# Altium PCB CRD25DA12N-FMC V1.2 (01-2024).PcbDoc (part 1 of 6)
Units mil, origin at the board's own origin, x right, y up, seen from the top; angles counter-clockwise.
Board outline 8000 x 8000 mil, 6 copper layers (Top Layer, Layer 2, Layer 3, Layer 4, Layer 5, Bottom Layer), stack 91 mil thick; 574 components, 325 nets, 1631 pads, 633 vias.
Unrouted connection lines stored in the file: 1.
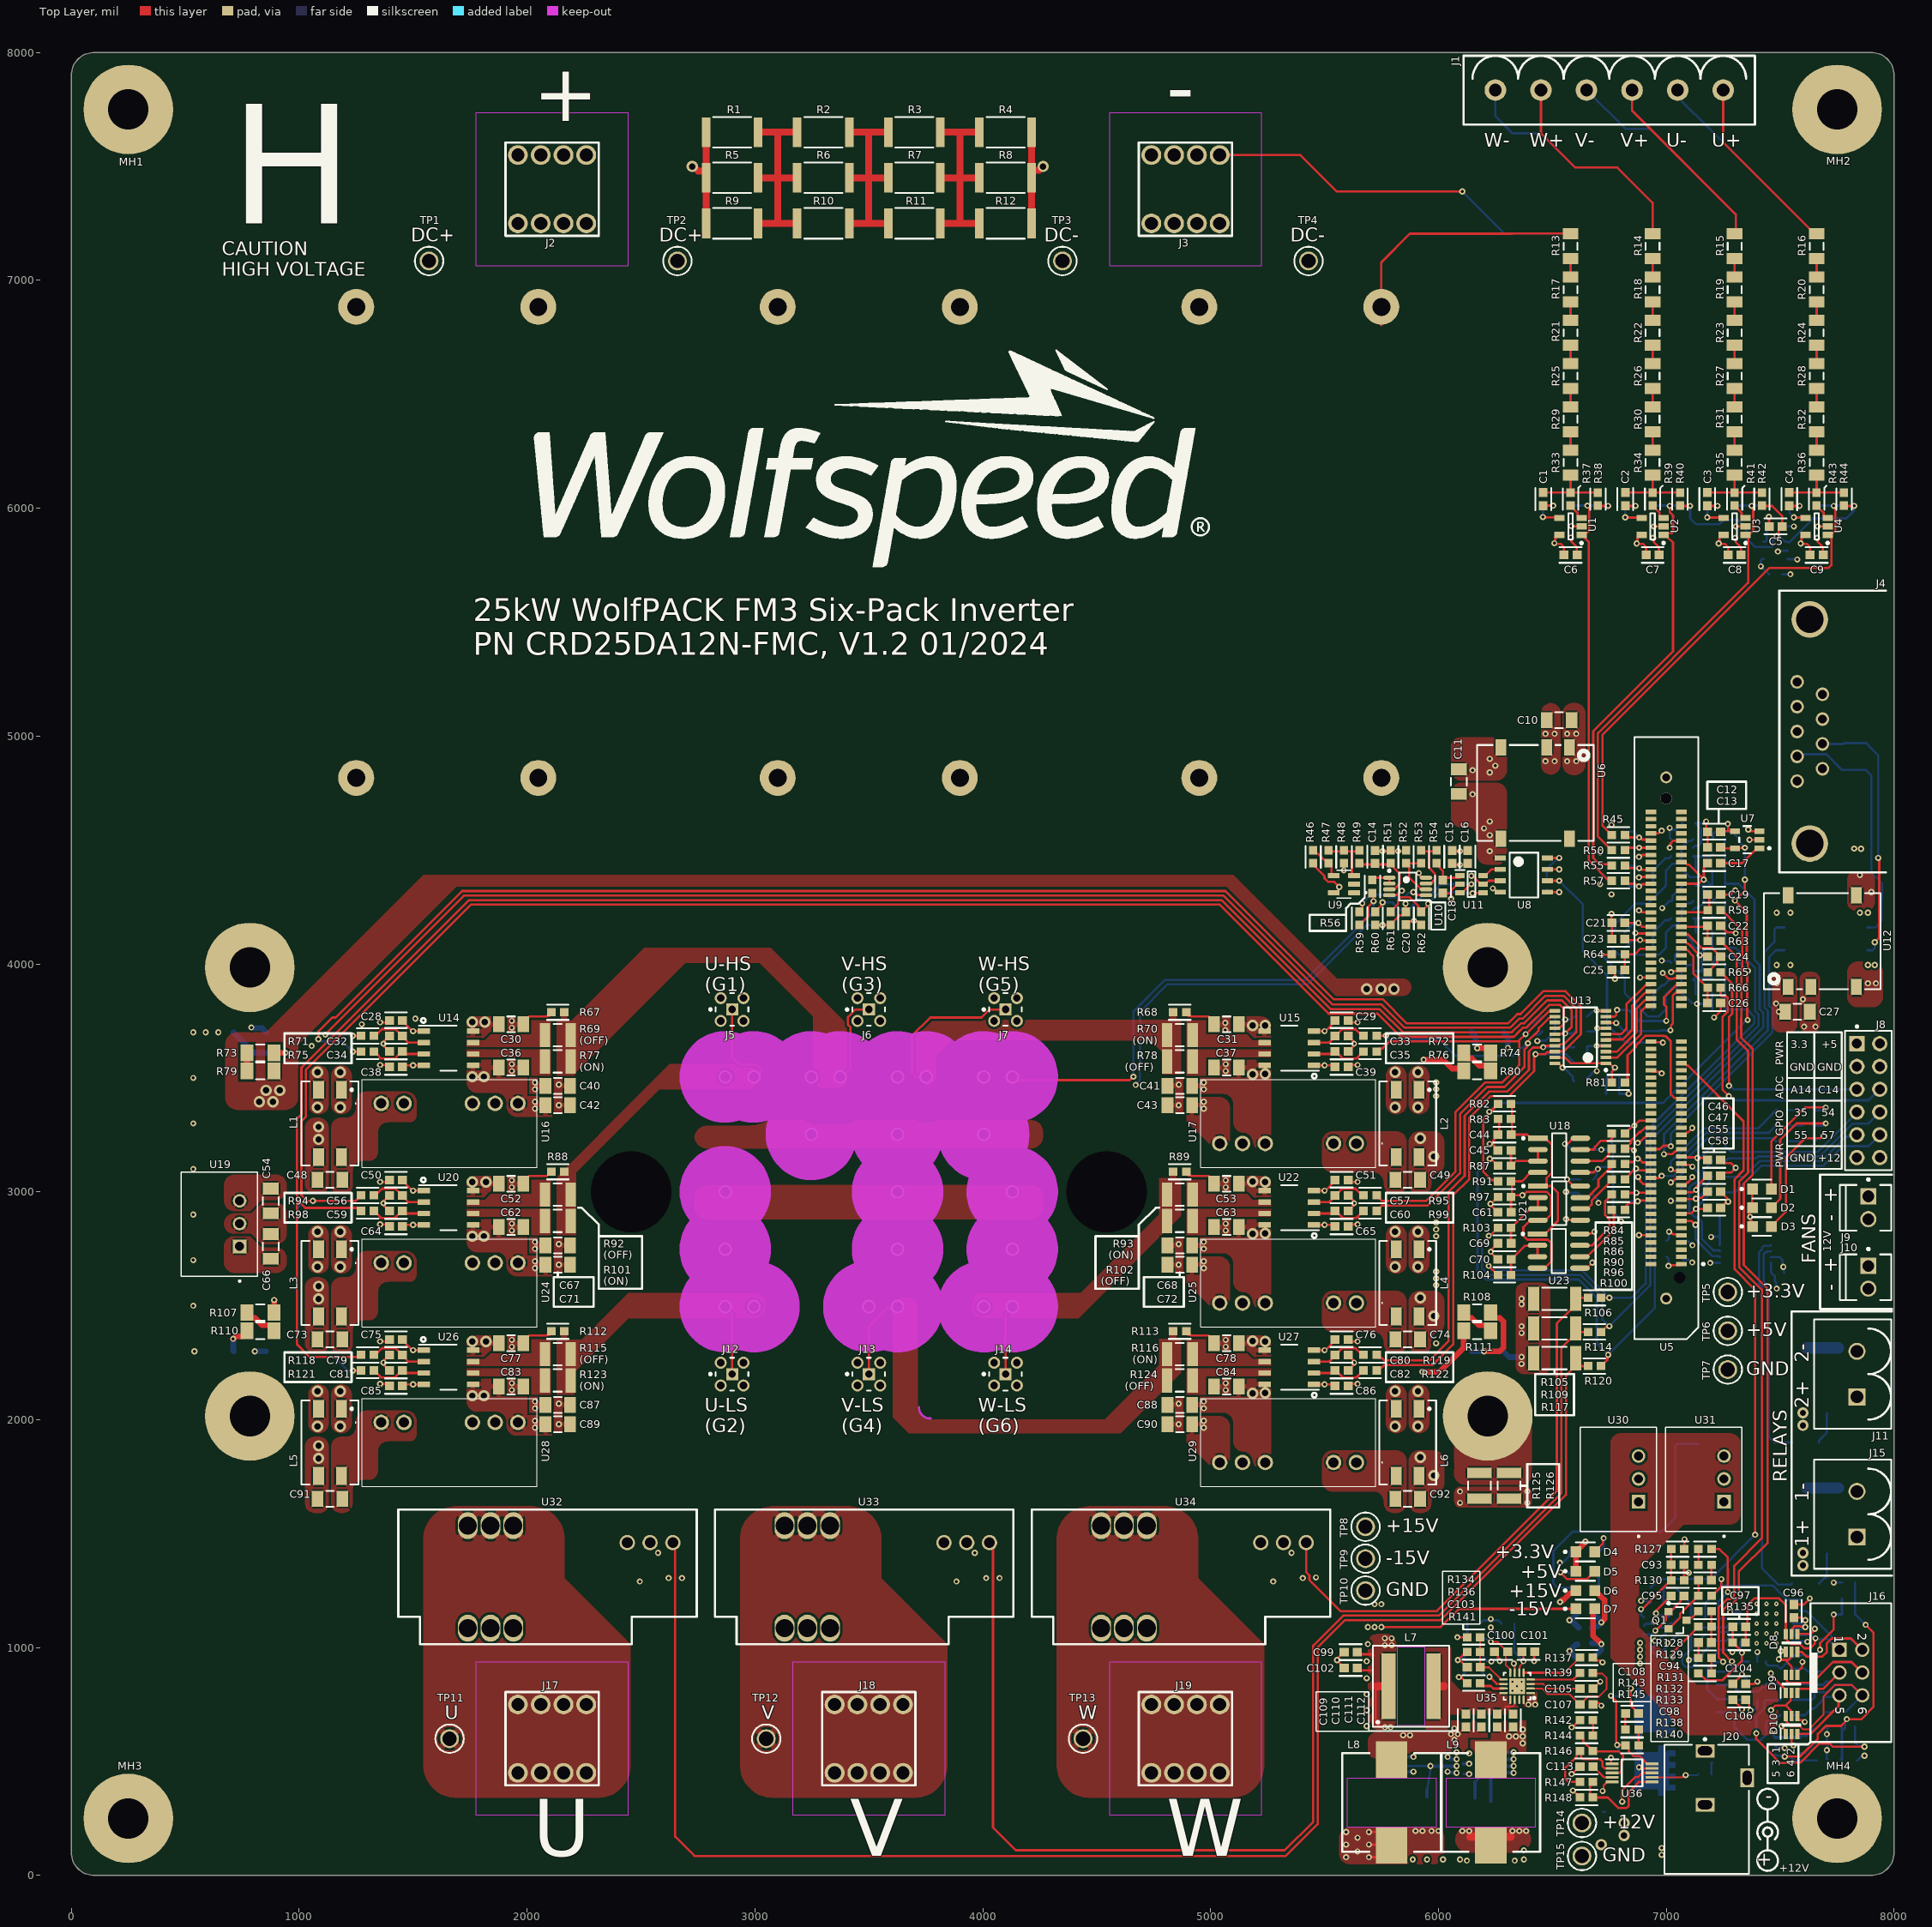
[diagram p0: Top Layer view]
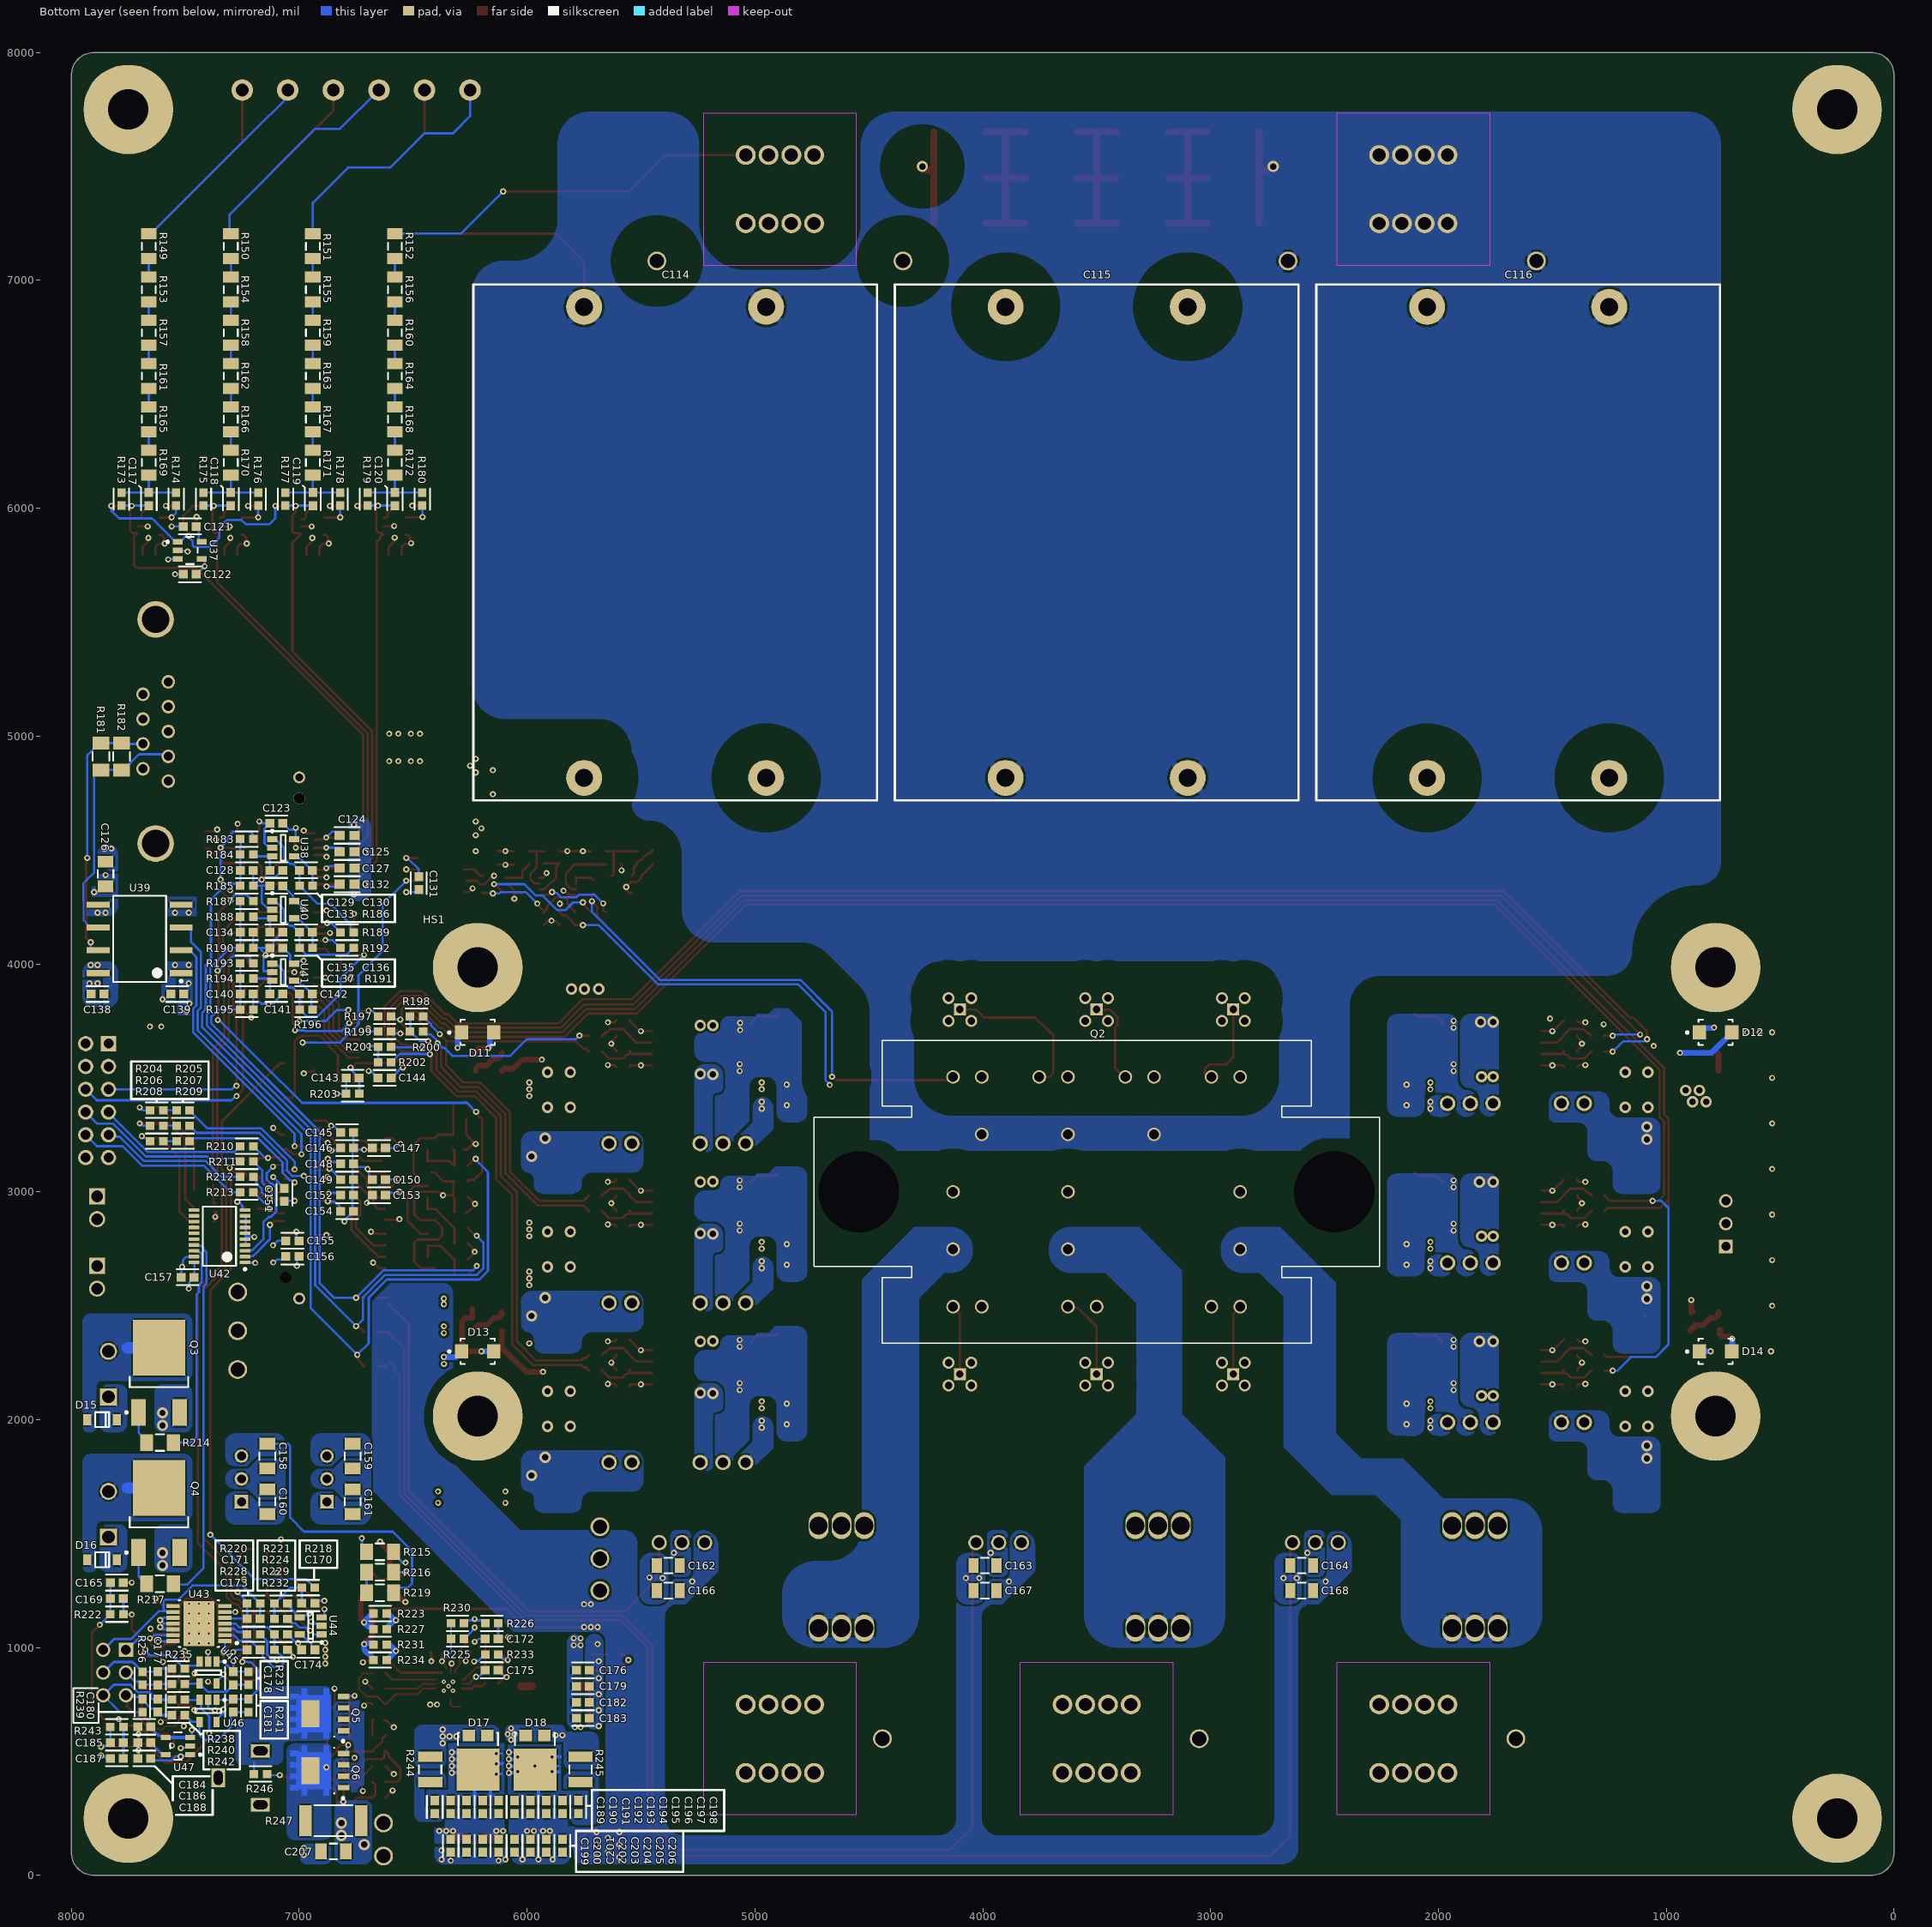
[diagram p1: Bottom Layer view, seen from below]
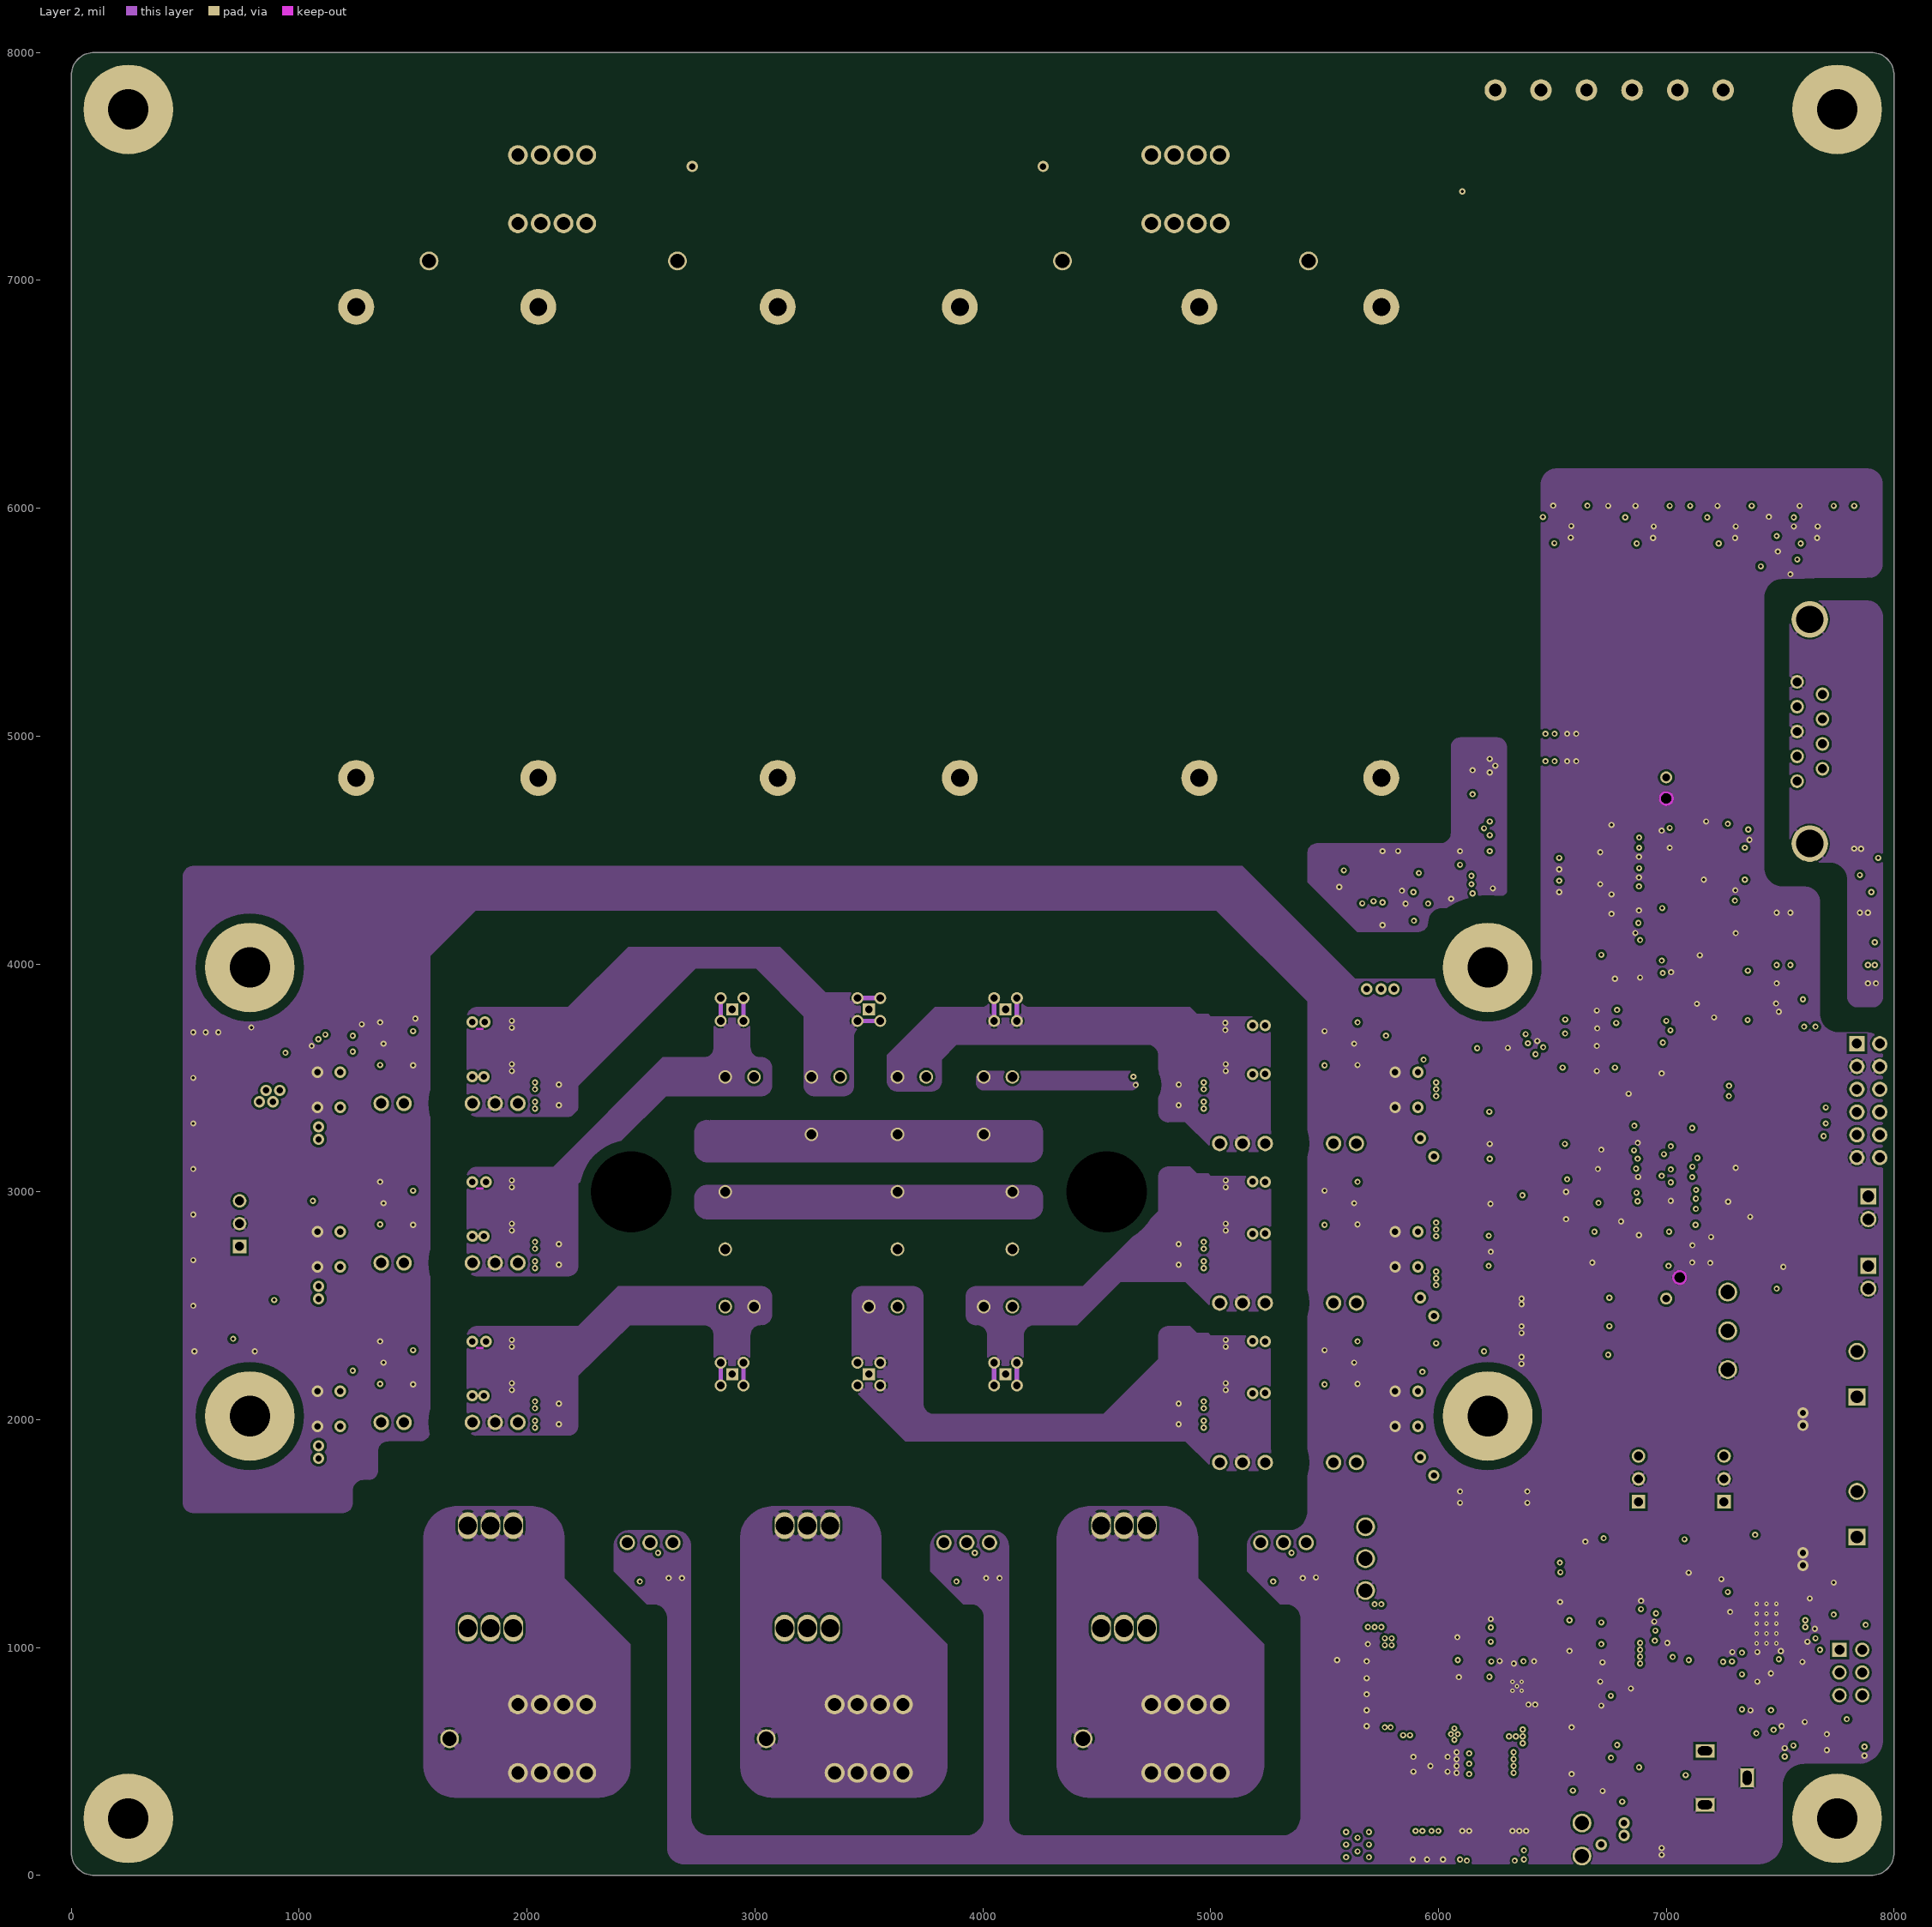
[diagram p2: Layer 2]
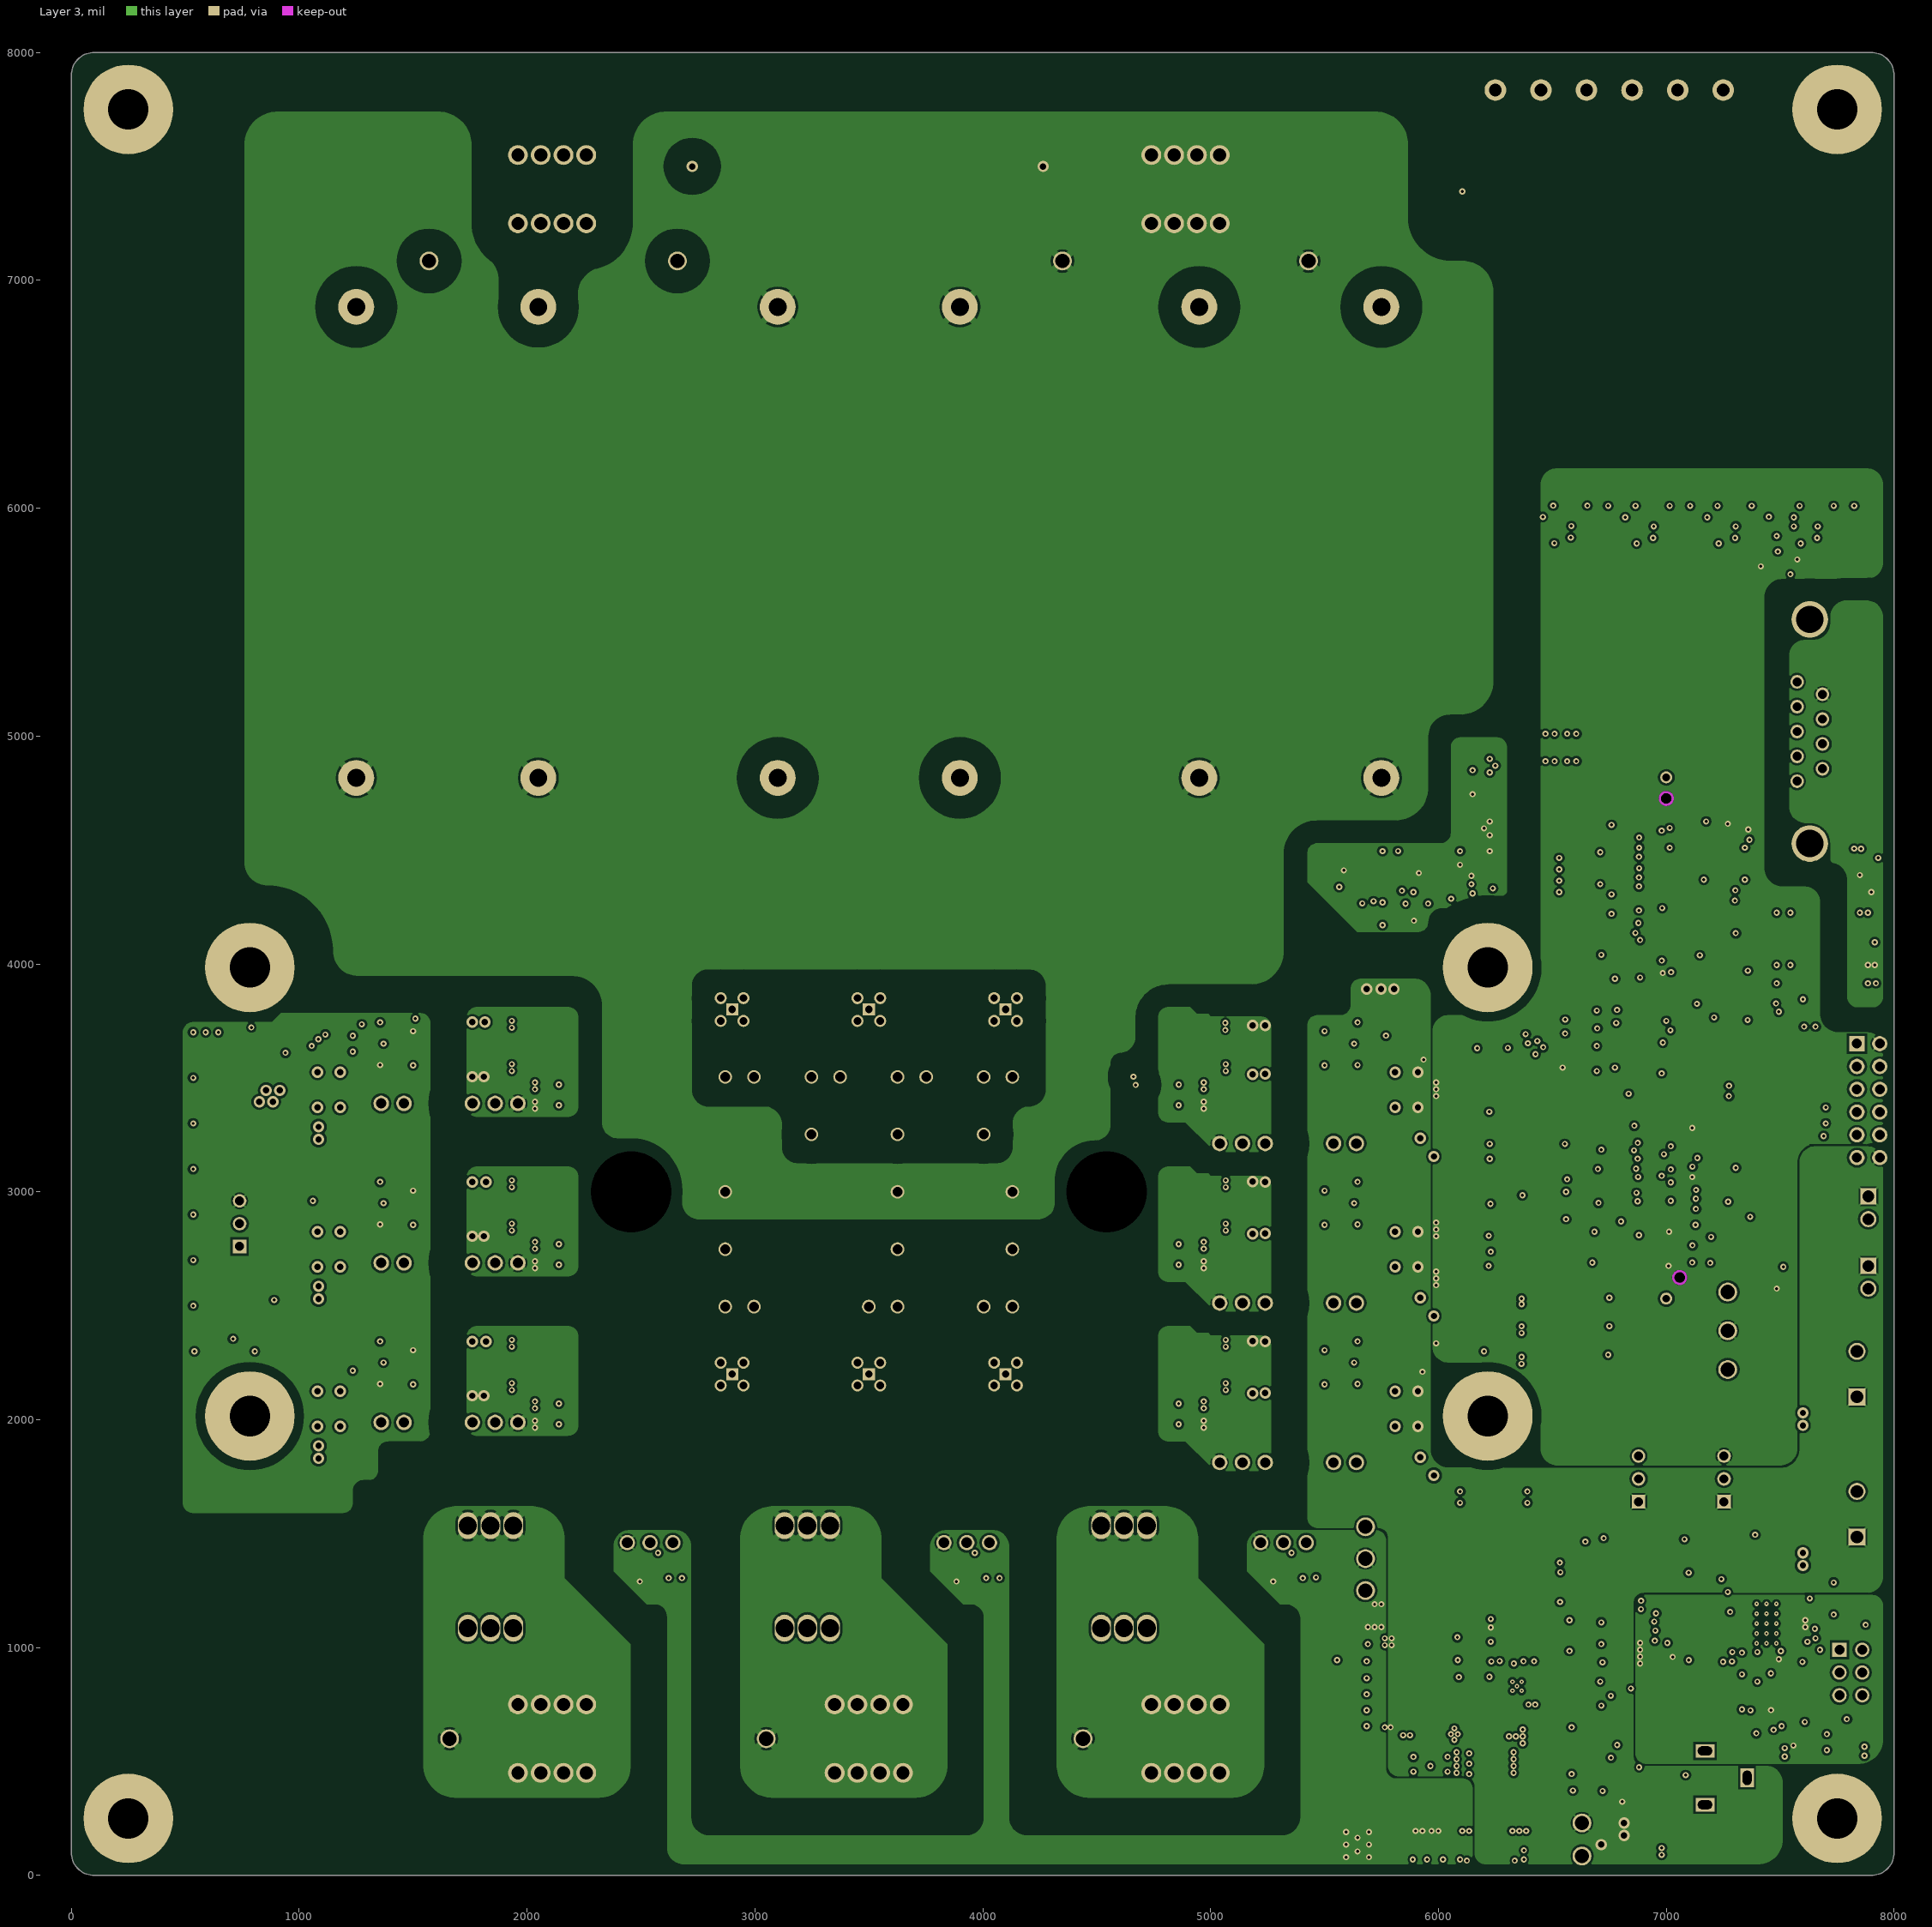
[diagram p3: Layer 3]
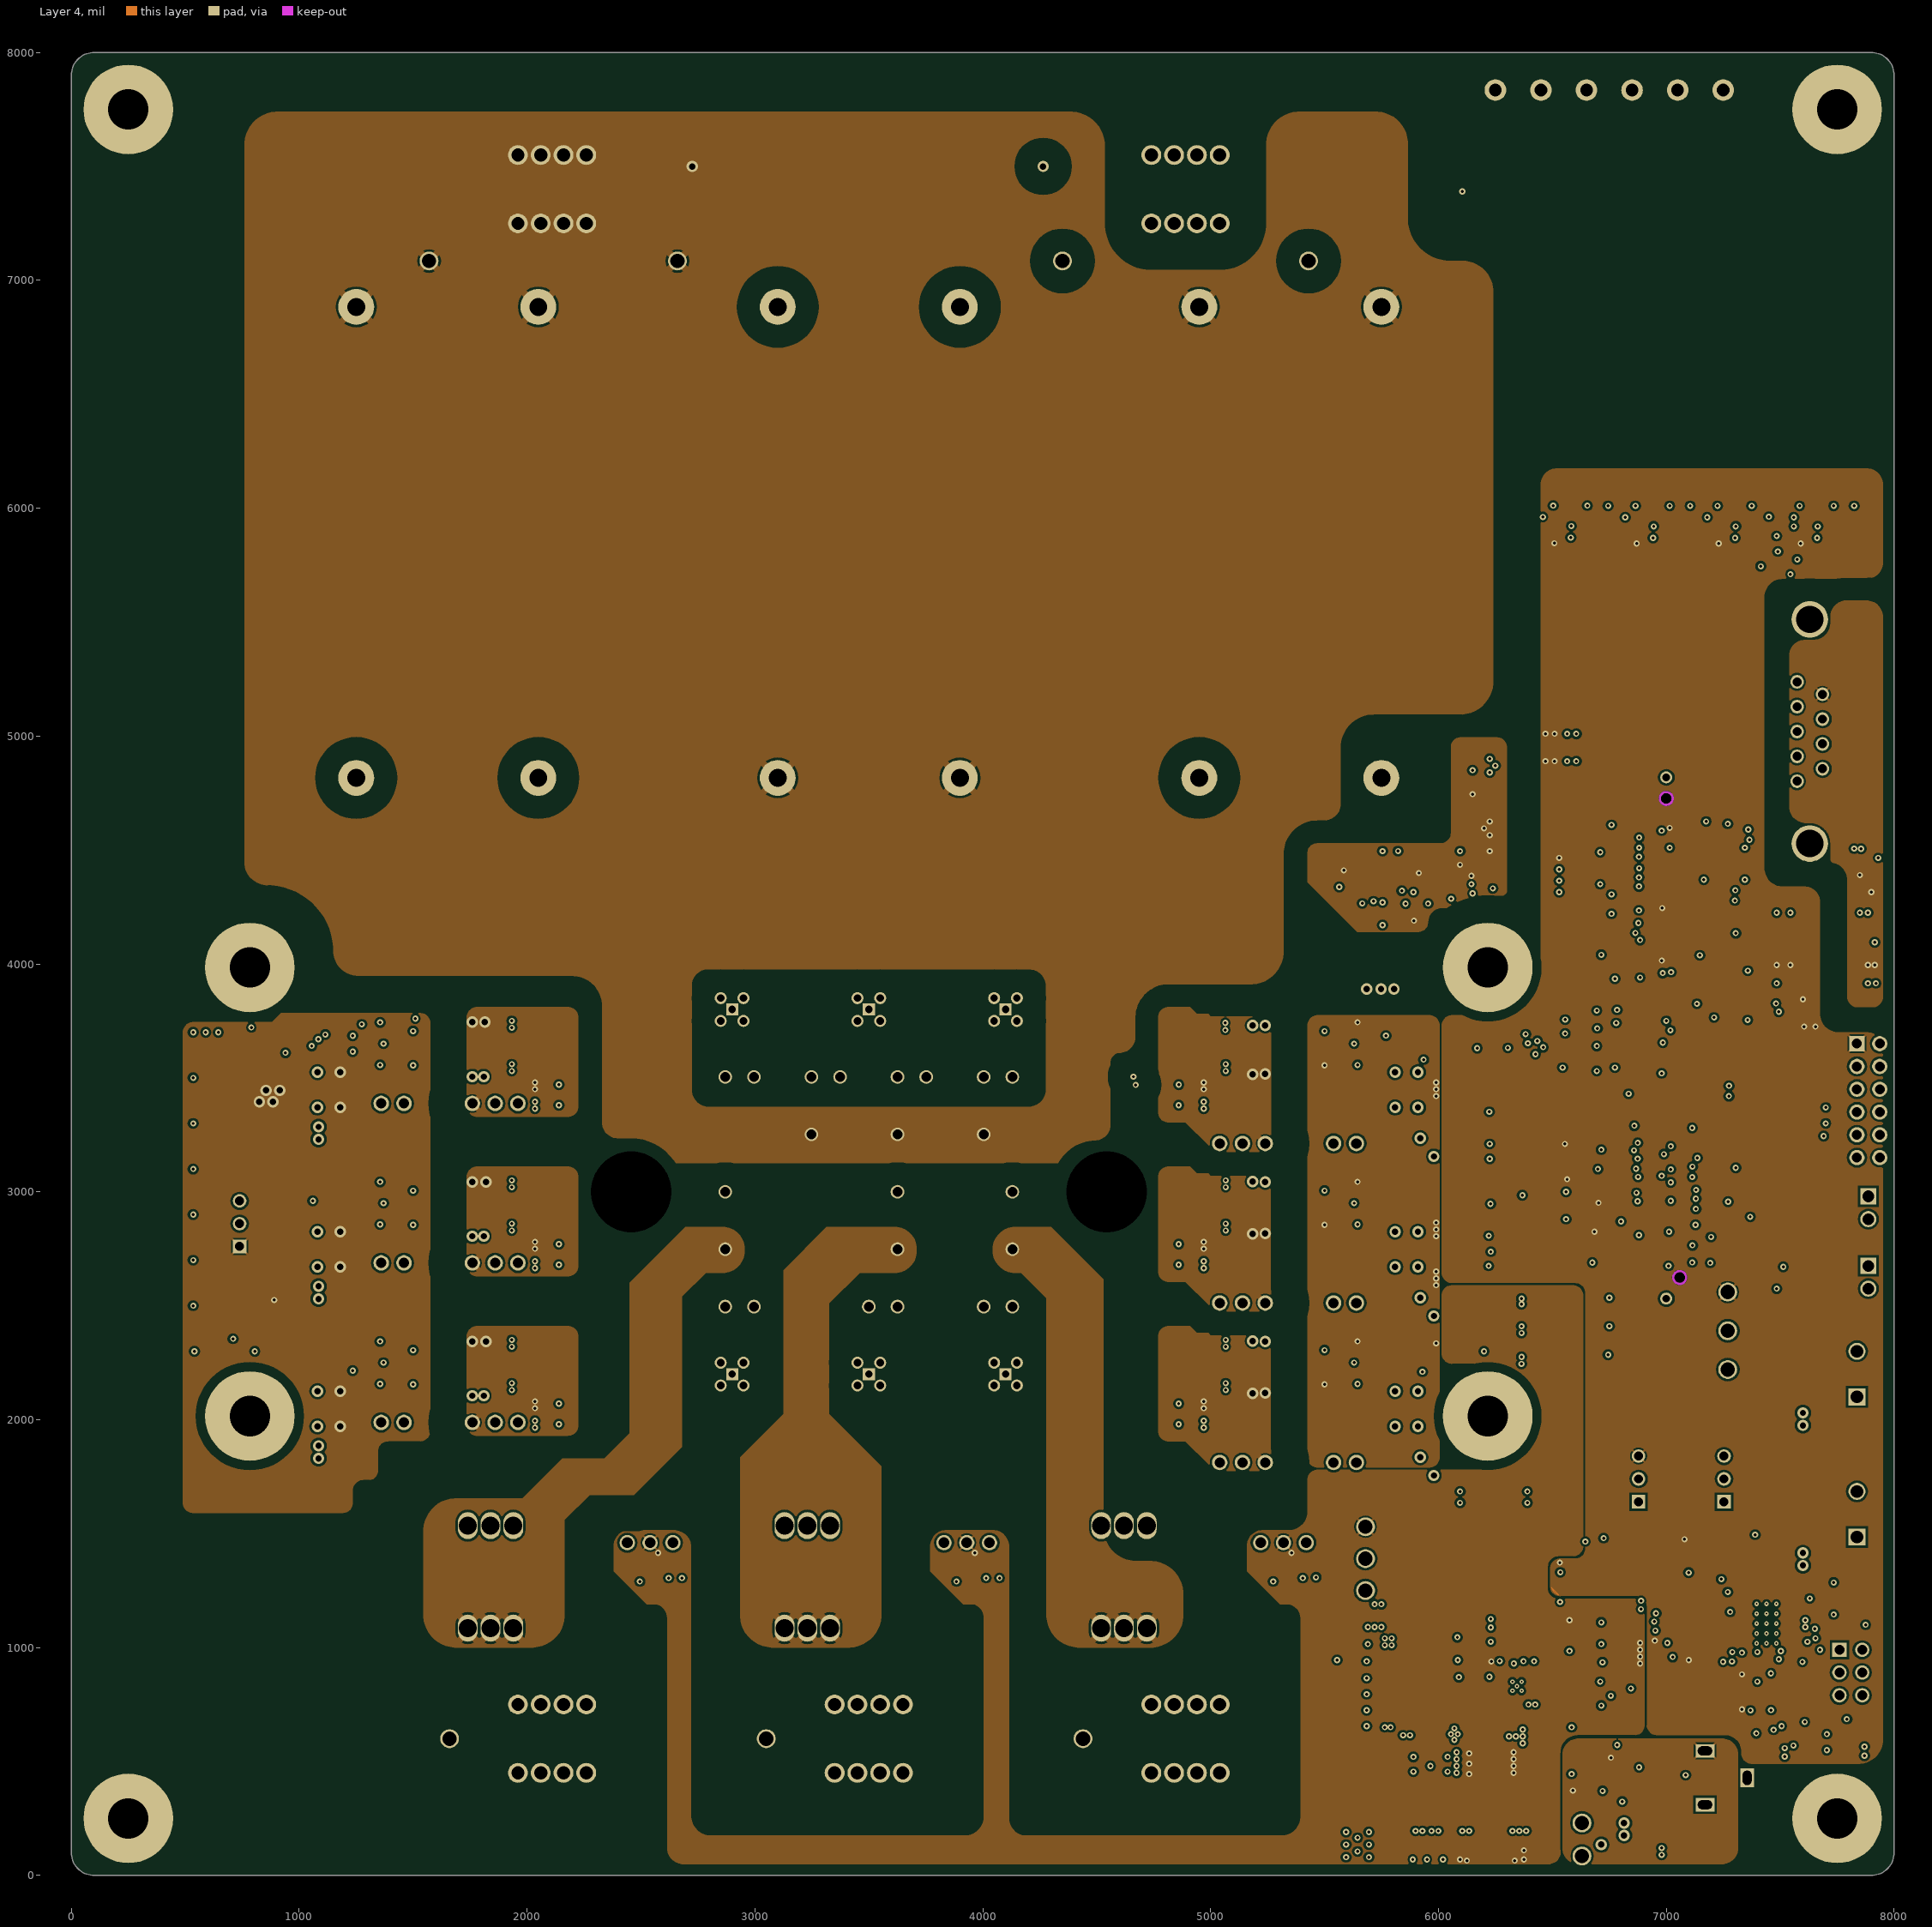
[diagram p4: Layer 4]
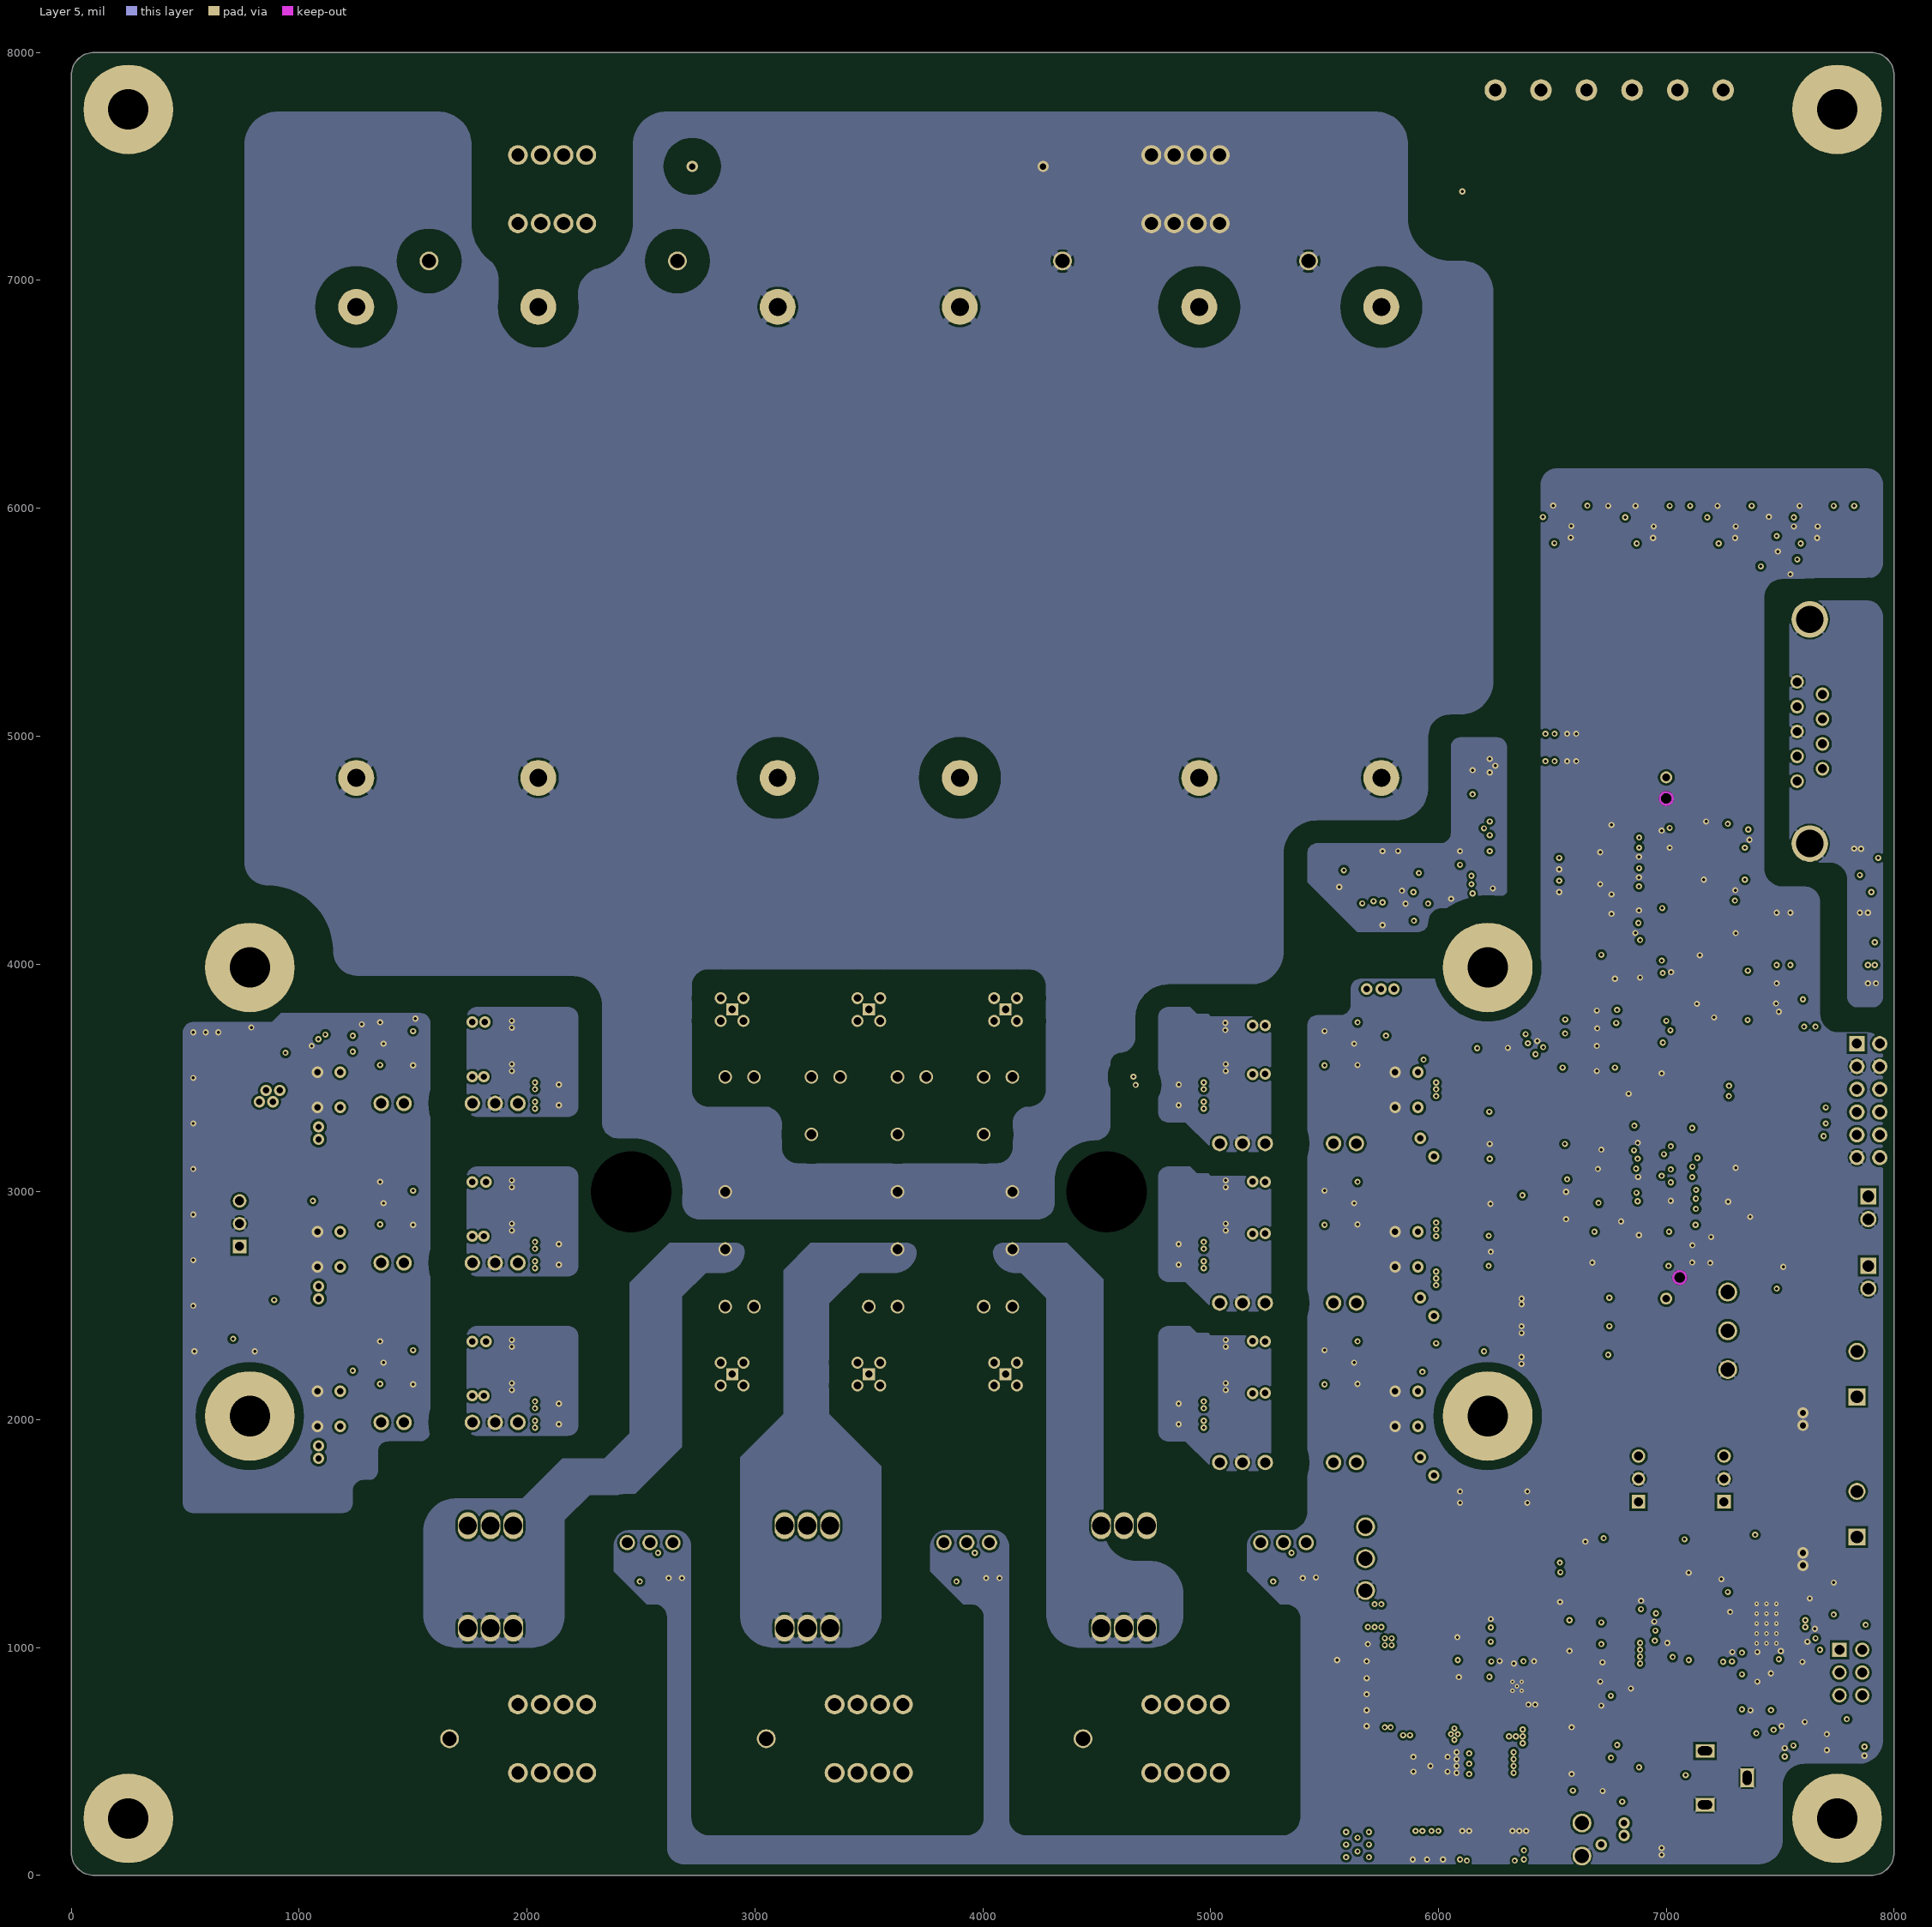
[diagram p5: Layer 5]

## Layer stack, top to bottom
Top Solder: solder mask 1, SM-002, Dk 4
Top Layer: signal copper 2.756
Dielectric 2: prepreg 7.894, PP-006, Dk 4.1
Layer 2: signal copper 2.756
Dielectric 4: prepreg 7.894, PP-006, Dk 4.1
Layer 3: signal copper 2.756
Dielectric 1: dielectric 42.888, FR-4, Dk 4.8
Layer 4: signal copper 2.756
Dielectric 5: prepreg 7.894, PP-006, Dk 4.1
Layer 5: signal copper 2.756
Dielectric 3: prepreg 7.894, PP-006, Dk 4.1
Bottom Layer: signal copper 2.756
Bottom Solder: solder mask 1, SM-002, Dk 4

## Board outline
0,100 0,7900 cw(c100,7900) 100,8000 7900,8000 cw(c7900,7900) 8000,7900 8000,100 cw(c7900,100) 7900,0 100,0 cw(c100,100)

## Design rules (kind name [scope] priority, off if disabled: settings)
Clearance Keepout [IsKeepOut] p1: gap=0 ignorepadtopadclearanceinfootprint=FALSE
Clearance DC+/-_Heatsink [InNet('DC-') Or InNet('DC+') vs HasFootprint('LA 6 150 12')] p2: gap=160 ignorepadtopadclearanceinfootprint=FALSE except(0: Arc-Hole Track-Hole SMDPad-Hole THPad-Hole Via-Hole Fill-Hole Poly-Hole Region-Hole Text-Hole)
Clearance NTC_Heatsink [InNetClass('NTC Class') vs HasFootprint('LA 6 150 12')] p3: gap=120 ignorepadtopadclearanceinfootprint=FALSE except(0: Arc-Hole Track-Hole SMDPad-Hole THPad-Hole Via-Hole Fill-Hole Poly-Hole Region-Hole Text-Hole)
Clearance Heatsink [All vs HasFootprint('LA 6 150 12')] p4: gap=40 ignorepadtopadclearanceinfootprint=FALSE except(0: Arc-Hole Track-Hole SMDPad-Hole THPad-Hole Via-Hole Fill-Hole Poly-Hole Region-Hole Text-Hole)
Clearance Module_Mount [All vs HoleDiameter = 354.331] p5: gap=50 ignorepadtopadclearanceinfootprint=FALSE
Clearance LV_to_G [InNetClass('LV Pours') vs InNetClass('Gate Class')] p6: gap=160 ignorepadtopadclearanceinfootprint=FALSE except(0: Arc-Hole Track-Hole SMDPad-Hole THPad-Hole Via-Hole Fill-Hole Poly-Hole Region-Hole Text-Hole)
Clearance DC+/-_to_LV [InNet('DC-') OR InNet('DC+') OR InNetClass('U Class') OR InNetClass('V Class') OR InNetClass('W Class') vs InNetClass('LV Pours')] p7: gap=160 ignorepadtopadclearanceinfootprint=FALSE except(0: Arc-Hole Track-Hole SMDPad-Hole THPad-Hole Via-Hole Fill-Hole Poly-Hole Region-Hole Text-Hole)
Clearance DC+_Internal [(InNet('DC-') Or InNetClass('DC+ Class')) AND InLayerClass('Internal Layers')] p8: gap=100 ignorepadtopadclearanceinfootprint=FALSE except(0: Arc-Hole Track-Hole SMDPad-Hole THPad-Hole Via-Hole Fill-Hole Poly-Hole Region-Hole Text-Hole)
Clearance DC+_Pins_External [InNet('DC+') AND InLayerClass('External Layers') vs (HasFootprint('FM3_SIX-PACK_3PHASE_CRW') OR HasFootprint('FP-73415-1471-MFG')) AND (InNetClass('Gate Class') OR InNetClass('NTC Class'))] p9: gap=140 ignorepadtopadclearanceinfootprint=FALSE except(0: Arc-Hole Track-Hole SMDPad-Hole THPad-Hole Via-Hole Fill-Hole Poly-Hole Region-Hole Text-Hole)
Clearance DC+_to_DC+ [InNetClass('DC+ Class') vs InNetClass('DC+ Class')] p10: gap=10 ignorepadtopadclearanceinfootprint=FALSE except(0: Arc-Hole Track-Hole SMDPad-Hole THPad-Hole Via-Hole Fill-Hole Poly-Hole Region-Hole Text-Hole)
Clearance DC+_External [InNet('DC+') AND InLayerClass('External Layers')] p11: gap=160 ignorepadtopadclearanceinfootprint=FALSE except(0: Arc-Text Arc-Hole Track-Text Track-Hole SMDPad-Text SMDPad-Hole THPad-Text THPad-Hole Via-Text Via-Hole Fill-Text Fill-Hole Poly-Text Poly-Hole Region-Text Region-Hole Text-Text Text-Hole)
Clearance CAN [InNetClass('CAN Class') vs Not InNetClass('CAN Class') And Not IsPad] p12: gap=100 ignorepadtopadclearanceinfootprint=FALSE except(0: Arc-Hole Track-Hole SMDPad-Hole THPad-Hole Via-Hole Fill-Hole Poly-Hole Region-Hole Text-Hole)
Clearance U [InNetClass('U Class') vs NOT InNetClass('U Class')] p13: gap=100 ignorepadtopadclearanceinfootprint=FALSE except(0: Arc-Text Arc-Hole Track-Text Track-Hole SMDPad-Text SMDPad-Hole THPad-Text THPad-Hole Via-Text Via-Hole Fill-Text Fill-Hole Poly-Text Poly-Hole Region-Text Region-Hole Text-Text Text-Hole)
Clearance V [InNetClass('V Class') vs NOT InNetClass('V Class')] p14: gap=100 ignorepadtopadclearanceinfootprint=FALSE except(0: Arc-Text Arc-Hole Track-Text Track-Hole SMDPad-Text SMDPad-Hole THPad-Text THPad-Hole Via-Text Via-Hole Fill-Text Fill-Hole Poly-Text Poly-Hole Region-Text Region-Hole Text-Text Text-Hole)
Clearance W [InNetClass('W Class') vs NOT InNetClass('W Class')] p15: gap=100 ignorepadtopadclearanceinfootprint=FALSE except(0: Arc-Hole Track-Hole SMDPad-Hole THPad-Hole Via-Hole Fill-Hole Poly-Hole Region-Hole Text-Text Text-Hole)
Clearance NTC_External [InNetClass('NTC Class') AND InLayerClass('External Layers') vs NOT InNetClass('NTC Class') AND NOT IsPad] p16: gap=150 ignorepadtopadclearanceinfootprint=FALSE except(0: Arc-Hole Track-Hole SMDPad-Hole THPad-Hole Via-Hole Fill-Hole Poly-Hole Region-Hole Text-Hole)
Clearance NTC_Internal [InNetClass('NTC Class') AND InLayerClass('Internal Layers') vs NOT InNetClass('NTC Class') AND NOT IsPad] p17: gap=100 ignorepadtopadclearanceinfootprint=FALSE except(0: Arc-Hole Track-Hole SMDPad-Hole THPad-Hole Via-Hole Fill-Hole Poly-Hole Region-Hole Text-Hole)
Clearance [All] p18: gap=10 ignorepadtopadclearanceinfootprint=TRUE except(0: Arc-Hole Track-Hole SMDPad-Hole THPad-Hole Via-Hole Fill-Poly Fill-Hole Poly-Hole Region-Hole Text-Hole; 6: Arc-SMDPad Track-SMDPad SMDPad-SMDPad THPad-THPad)
Height [All] p1: minheight=0 maxheight=4100 prefheight=500
HoleSize [All] p1: absolutevalues=TRUE maxlimit=400 minlimit=5 maxpercent=80.000 minpercent=20.000
MinimumSolderMaskSliver [All] p1: minsoldermaskwidth=1.5
PolygonConnect InductorConnect [HasFootprint('74437368220')] p1: connectstyle=Direct reliefconductorwidth=10 reliefentries=4 polygonreliefangle="90 Angle" airgapwidth=10
PolygonConnect BoltConnect [HoleDiameter=177.165] p2: thpad.connectstyle=Direct thpad.reliefconductorwidth=10 thpad.reliefentries=4 thpad.polygonreliefangle="90 Angle" thpad.airgapwidth=10 smdpad.connectstyle=Relief smdpad.reliefconductorwidth=10 smdpad.reliefentries=4 smdpad.polygonreliefangle="90 Angle" smdpad.airgapwidth=10 via.connectstyle=Relief via.reliefconductorwidth=10 via.reliefentries=4 via.polygonreliefangle="90 Angle" via.airgapwidth=10
PolygonConnect PressFitConnect [HasFootprint('7460307')] p3: connectstyle=Direct reliefconductorwidth=10 reliefentries=4 polygonreliefangle="90 Angle" airgapwidth=10
PolygonConnect ModuleConnect [HasFootprint('FM3_SIX-PACK_3PHASE_CRW')] p4: connectstyle=Direct reliefconductorwidth=30 reliefentries=4 polygonreliefangle="45 Angle" airgapwidth=10
PolygonConnect PourOverThruConnect [InNetClass('Pour-Over Thru Class') AND NOT HasFootprint('FM3_SIX-PACK_3PHASE_CRW')] p5: thpad.connectstyle=Relief thpad.reliefconductorwidth=20 thpad.reliefentries=4 thpad.polygonreliefangle="45 Angle" thpad.airgapwidth=7 smdpad.connectstyle=Relief smdpad.reliefconductorwidth=20 smdpad.reliefentries=4 smdpad.polygonreliefangle="90 Angle" smdpad.airgapwidth=8 via.connectstyle=Direct via.reliefconductorwidth=10 via.reliefentries=4 via.polygonreliefangle="90 Angle" via.airgapwidth=10
PolygonConnect PourOverConnect [InNetClass('Pour-Over Class')] p6: connectstyle=Direct reliefconductorwidth=10 reliefentries=4 polygonreliefangle="90 Angle" airgapwidth=10
PolygonConnect ViaConnect [IsVia] p7: connectstyle=Direct reliefconductorwidth=10 reliefentries=4 polygonreliefangle="90 Angle" airgapwidth=10
PolygonConnect HighCurrentThermalConnect [InNetClass('High-Current Class') AND NOT HasFootprint('FM3_SIX-PACK_3PHASE_CRW')] p8: thpad.connectstyle=Relief thpad.reliefconductorwidth=30 thpad.reliefentries=4 thpad.polygonreliefangle="45 Angle" thpad.airgapwidth=10 smdpad.connectstyle=Relief smdpad.reliefconductorwidth=10 smdpad.reliefentries=4 smdpad.polygonreliefangle="45 Angle" smdpad.airgapwidth=10 via.connectstyle=Direct via.reliefconductorwidth=10 via.reliefentries=4 via.polygonreliefangle="90 Angle" via.airgapwidth=10
PolygonConnect [All] p9: connectstyle=Relief reliefconductorwidth=10 reliefentries=4 polygonreliefangle="45 Angle" airgapwidth=7
RoutingVias [All] p1: holewidth=28 width=50 viastyle="Through Hole" minholewidth=28 minwidth=50 maxholewidth=28 maxwidth=50
SilkToSilkClearance [All] p1: silktosilkclearance=4
SilkToSolderMaskClearance [IsPad] p1: minsilkscreentomaskgap=2 clearancetoexposedcopper=TRUE
SolderMaskExpansion [All] p1: expansion=4 istentingtop=FALSE
Width [All] p1: maxlimit=100 minlimit=6.5 preferedwidth=10 minimp=50.000000 maximp=50.000000 favimp=50.000000
25 further rules are at their usual default settings.

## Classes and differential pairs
net class "Gate Class": +15V_U_HS +15V_U_LS +15V_V_HS +15V_V_LS +15V_W_HS +15V_W_LS -3V_U_HS -3V_U_LS -3V_V_HS -3V_V_LS -3V_W_HS -3V_W_LS G1 G1H G1L G2 G2H G2L G3 G3H G3L G4 G4H G4L G5 G5H G5L G6 G6H G6L S1 S2 S3 S4 S5 S6
net class "LV Pours": +3.3V +5V +5V_ALT +12V +15V -15V GND
net class "DC+ Class": DC+ DC+1
net class "G6 Class": +15V_W_LS -3V_W_LS G6 G6H G6L S6
net class "G5 Class": +15V_W_HS -3V_W_HS G5 G5H G5L S5
net class "G4 Class": +15V_V_LS -3V_V_LS G4 G4H G4L S4
net class "G3 Class": +15V_V_HS -3V_V_HS G3 G3H G3L S3
net class "G2 Class": +15V_U_LS -3V_U_LS G2 G2H G2L S2
net class "G1 Class": +15V_U_HS -3V_U_HS G1 G1H G1L S1
net class "CAN Class": +5V_ISO CAN_H CAN_L GND_ISO
net class "NTC Class": +5V_NTC GND_NTC NTC1 NTC1_BUF NTC1_FB NTC1_INV NTC_B0 NTC_B1 NTC_BIAS NTC_BIAS_BUF NTC_DIV NTC_MOD NTC_PWM NTC_SET
net class "Pour-Over Thru Class": +15V_U_HS +15V_U_LS +15V_V_HS +15V_V_LS +15V_W_HS +15V_W_LS -3V_U_HS -3V_U_LS -3V_V_HS -3V_V_LS -3V_W_HS -3V_W_LS S1 S2 S3 S4 S5 S6
net class "Pour-Over Class": G1 G1H G1L G2 G2H G2L G3 G3H G3L G4 G4H G4L G5 G5H G5L G6 G6H G6L
net class "High-Current Class": DC+ DC- U U_OUT V V_OUT W W_OUT
net class "Bleed Class": BLEED1 BLEED2 BLEED3
net class "DC- Class": +15V_U_LS +15V_V_LS +15V_W_LS -3V_U_LS -3V_V_LS -3V_W_LS DC- G2 G2H G2L G4 G4H G4L G6 G6H G6L S2 S4 S6
net class "W Class": +15V_W_HS -3V_W_HS G5 G5H G5L S5 W W_OUT
net class "V Class": +15V_V_HS -3V_V_HS G3 G3H G3L S3 V V_OUT
net class "U Class": +15V_U_HS -3V_U_HS G1 G1H G1L S1 U U_OUT
component class "08 - Resolver": C19 C22 C93 C94 C95 C96 C97 C98 C104 C106 C165 C169 C170 C171 C173 C174 C177 C178 C180 C181 C185 C187 D8 D9 D10 J16 Q1 R58 R63 R127 R128 R129 R130 R131 R132 R133 R135 R138 R140 R218 R220 R221 R222 R224 R228 R229 R232 R235 R236 R237 R238 R239 R240 R241 R242 R243 U43 U44 U45 U46
component class "02 - Power Stage": C114 C115 C116 C162 C163 C164 C166 C167 C168 D11 D12 D13 D14 HS1 J2 J3 J5 J6 J7 J12 J13 J14 J17 J18 J19 MH1 MH2 MH3 MH4 Q2 R1 R2 R3 R4 R5 R6 R7 R8 R9 R10 R11 R12 R73 R74 R79 R80 R107 R108 R110 R111 R125 R126 TP1 TP2 TP3 TP4 TP11 TP12 TP13 U32 U33 U34
component class "04 - Auxiliary Power": C5 C10 C11 C12 C13 C17 C27 C54 C66 C99 C100 C101 C102 C103 C105 C107 C108 C109 C110 C111 C112 C113 C121 C122 C126 C158 C159 C160 C161 C172 C175 C176 C179 C182 C183 C184 C186 C188 C189 C190 C191 C192 C193 C194 C195 C196 C197 C198 C199 C200 C201 C202 C203 C204 C205 C206 C207 D4 D5 D6 D7 D17 D18 J9 J10 J20 L7 L8 L9 Q5 Q6 R134 R136 R137 R139 R141 R142 R143 R144 R145 R146 R147 R148 R215 R216 R219 R223 R225 R226 R227 R230 R231 R233 R234 R244 R245 R246 R247 TP5 TP6 TP7 TP8 TP9 TP10 TP14 TP15 U6 U7 U12 U19 U30 U31 U35 U36 U37 U47
component class "07 - Current Sense": C21 C23 C25 C44 C45 C61 C69 C70 C123 C128 C129 C130 C133 C134 C135 C136 C137 C140 C141 C142 C145 C146 C147 C148 C149 C150 C152 C153 C154 R64 R82 R83 R84 R85 R86 R87 R90 R91 R96 R97 R100 R103 R104 R105 R106 R109 R114 R117 R120 R183 R184 R185 R186 R187 R188 R189 R190 R191 R192 R193 R194 R195 R196 U18 U21 U23 U38 U40 U41
component class "03 - Controller": C24 C26 C46 C47 C55 C58 C138 C139 C151 C155 C156 C157 D1 D2 D3 D15 D16 J4 J8 J11 J15 Q3 Q4 R65 R66 R181 R182 R204 R205 R206 R207 R208 R209 R210 R211 R212 R213 R214 R217 U5 U39 U42
component class "06 - Voltage Sense": C1 C2 C3 C4 C6 C7 C8 C9 C117 C118 C119 C120 C124 C125 C127 C132 J1 R13 R14 R15 R16 R17 R18 R19 R20 R21 R22 R23 R24 R25 R26 R27 R28 R29 R30 R31 R32 R33 R34 R35 R36 R37 R38 R39 R40 R41 R42 R43 R44 R45 R50 R55 R57 R149 R150 R151 R152 R153 R154 R155 R156 R157 R158 R159 R160 R161 R162 R163 R164 R165 R166 R167 R168 R169 R170 R171 R172 R173 R174 R175 R176 R177 R178 R179 R180 U1 U2 U3 U4
component class "05 - Gate Drivers": C14 C15 C16 C18 C20 C28 C29 C30 C31 C32 C33 C34 C35 C36 C37 C38 C39 C40 C41 C42 C43 C48 C49 C50 C51 C52 C53 C56 C57 C59 C60 C62 C63 C64 C65 C67 C68 C71 C72 C73 C74 C75 C76 C77 C78 C79 C80 C81 C82 C83 C84 C85 C86 C87 C88 C89 C90 C91 C92 C131 C143 C144 L1 L2 L3 L4 L5 L6 R46 R47 R48 R49 R51 R52 R53 R54 R56 R59 R60 R61 R62 R67 R68 R69 R70 R71 R72 R75 R76 R77 R78 R81 R88 R89 R92 R93 R94 R95 R98 R99 R101 R102 R112 R113 R115 R116 R118 R119 R121 R122 R123 R124 R197 R198 R199 R200 R201 R202 R203 U8 U9 U10 U11 U13 U14 U15 U16 U17 U20 U22 U24 U25 U26 U27 U28 U29

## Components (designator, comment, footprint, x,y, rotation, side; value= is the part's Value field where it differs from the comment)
C1 "C0603C472K3RAC7867" FP-C0603C-CF-IPC_B 6460,6040 r270 top value=4.7nF
C2 "CL10B103KA8WPNC" FP-C0603C-CF-IPC_B 6820,6040 r270 top value=10nF
C3 "CL10B103KA8WPNC" FP-C0603C-CF-IPC_B 7180,6040 r270 top value=10nF
C4 "CL10B103KA8WPNC" FP-C0603C-CF-IPC_B 7540,6040 r270 top value=10nF
C5 "C0603C104K3RACTU" FP-C0603C-CF-IPC_B 7480,5920 r180 top value=0.10μF
C6 "C0603C104K3RACTU" FP-C0603C-CF-IPC_B 6580,5795 r0 top value=0.10μF
C7 "C0603C104K3RACTU" FP-C0603C-CF-IPC_B 6940,5795 r0 top value=0.10μF
C8 "C0603C104K3RACTU" FP-C0603C-CF-IPC_B 7300,5795 r0 top value=0.10μF
C9 "C0603C104K3RACTU" FP-C0603C-CF-IPC_B 7660,5795 r0 top value=0.10μF
C10 "CL31B106KAHSFNE" FP-CL31-IPC_B 6530,5070 r0 top value=10μF
C11 "CL31B106KAHSFNE" FP-CL31-IPC_B 6090,4800 r90 top value=10μF
C12 "C0603C104K3RACTU" FP-C0603C-CF-IPC_B 7210,4580 r180 top value=0.10μF
C13 "C0603C104K3RACTU" FP-C0603C-CF-IPC_B 7210,4511 r180 top value=0.10μF
C14 "C0603C104K3RACTU" FP-C0603C-CF-IPC_B 5722,4470 r90 top value=0.10μF
C15 "C0603C104K3RACTU" FP-C0603C-CF-IPC_B 6060,4470 r90 top value=0.10μF
C16 "C0603C104K3RACTU" FP-C0603C-CF-IPC_B 6128,4470 r90 top value=0.10μF
C17 "C0603C104K3RACTU" FP-C0603C-CF-IPC_B 7210,4442 r180 top value=0.10μF
C18 "C0603C104K3RACTU" FP-C0603C-CF-IPC_B 6020,4340 r270 top value=0.10μF
C19 "C0603C102K5RACAUTO" FP-C0603C-CF-IPC_B 7210,4304 r0 top value=1nF
C20 "C0603C104K3RACTU" FP-C0603C-CF-IPC_B 5858,4200 r90 top value=0.10μF
C21 "C0603C472K3RAC7867" FP-C0603C-CF-IPC_B 6790,4180 r180 top value=4.7nF
C22 "C0603C102K5RACAUTO" FP-C0603C-CF-IPC_B 7210,4168 r0 top value=1nF
C23 "C0603C472K3RAC7867" FP-C0603C-CF-IPC_B 6790,4110 r180 top value=4.7nF
C24 "CL10C560JB8NNNC" FP-C0603C-CF-IPC_B 7210,4032 r180 top value=56pF
C25 "C0603C472K3RAC7867" FP-C0603C-CF-IPC_B 6790,3974 r180 top value=4.7nF
C26 "CL10C560JB8NNNC" FP-C0603C-CF-IPC_B 7210,3828 r0 top value=56pF
C27 "CL31B106KAHSFNE" FP-CL31-IPC_B 7575.81,3790 r180 top value=10μF
C28 "GRT188R61H225ME13D" FP-C0603C-CF-IPC_B 1425,3752 r180 top value=2.2μF
C29 "GRT188R61H225ME13D" FP-C0603C-CF-IPC_B 5575,3752 r180 top value=2.2μF
C30 "CL31B106KAHSFNE" FP-CL31-IPC_B 1930,3735 r180 top value=10μF
C31 "CL31B106KAHSFNE" FP-CL31-IPC_B 5070,3735 r180 top value=10μF
C32 "CL10C560JB8NNNC" FP-C0603C-CF-IPC_B 1425,3684 r180 top value=56pF
C33 "CL10C560JB8NNNC" FP-C0603C-CF-IPC_B 5575,3684 r0 top value=56pF
C34 "CL10C560JB8NNNC" FP-C0603C-CF-IPC_B 1425,3616 r180 top value=56pF
C35 "CL10C560JB8NNNC" FP-C0603C-CF-IPC_B 5575,3616 r0 top value=56pF
C36 "CL31B106KAHSFNE" FP-CL31-IPC_B 1930,3545 r0 top value=10μF
C37 "CL31B106KAHSFNE" FP-CL31-IPC_B 5070,3545 r0 top value=10μF
C38 "GRT188R61H225ME13D" FP-C0603C-CF-IPC_B 1425,3548 r0 top value=2.2μF
C39 "GRT188R61H225ME13D" FP-C0603C-CF-IPC_B 5575,3548 r0 top value=2.2μF
C40 "CL31B106KAHSFNE" FP-CL31-IPC_B 2135,3465 r180 top value=10μF
C41 "CL31B106KAHSFNE" FP-CL31-IPC_B 4865,3465 r0 top value=10μF
C42 "CL31B106KAHSFNE" FP-CL31-IPC_B 2135,3380 r0 top value=10μF
C43 "CL31B106KAHSFNE" FP-CL31-IPC_B 4865,3380 r180 top value=10μF
C44 "C0603C104K3RACTU" FP-C0603C-CF-IPC_B 6290,3251 r180 top value=0.10μF
C45 "C0603C472K3RAC7867" FP-C0603C-CF-IPC_B 6290,3182 r180 top value=4.7nF
C46 "CL10C560JB8NNNC" FP-C0603C-CF-IPC_B 7210,3140 r0 top value=56pF
C47 "CL10C560JB8NNNC" FP-C0603C-CF-IPC_B 7210,3070 r0 top value=56pF
C48 "CL31B106KAHSFNE" FP-CL31-IPC_B 1135,3052 r180 top value=10μF
C49 "CL31B106KAHSFNE" FP-CL31-IPC_B 5865,3052 r180 top value=10μF
C50 "GRT188R61H225ME13D" FP-C0603C-CF-IPC_B 1425,3052 r180 top value=2.2μF
C51 "GRT188R61H225ME13D" FP-C0603C-CF-IPC_B 5575,3052 r180 top value=2.2μF
C52 "CL31B106KAHSFNE" FP-CL31-IPC_B 1930,3035 r180 top value=10μF
C53 "CL31B106KAHSFNE" FP-CL31-IPC_B 5070,3035 r180 top value=10μF
C54 "CL31B106KAHSFNE" FP-CL31-IPC_B 875,2960 r270 top value=10μF
C55 "CL10C560JB8NNNC" FP-C0603C-CF-IPC_B 7210,3000 r0 top value=56pF
C56 "CL10C560JB8NNNC" FP-C0603C-CF-IPC_B 1425,2984 r180 top value=56pF
C57 "CL10C560JB8NNNC" FP-C0603C-CF-IPC_B 5575,2984 r0 top value=56pF
C58 "CL10C560JB8NNNC" FP-C0603C-CF-IPC_B 7210,2930 r0 top value=56pF
C59 "CL10C560JB8NNNC" FP-C0603C-CF-IPC_B 1425,2916 r180 top value=56pF
C60 "CL10C560JB8NNNC" FP-C0603C-CF-IPC_B 5575,2916 r0 top value=56pF
C61 "C0603C104K3RACTU" FP-C0603C-CF-IPC_B 6290,2909.96 r180 top value=0.10μF
C62 "CL31B106KAHSFNE" FP-CL31-IPC_B 1930,2845 r0 top value=10μF
C63 "CL31B106KAHSFNE" FP-CL31-IPC_B 5070,2845 r0 top value=10μF
C64 "GRT188R61H225ME13D" FP-C0603C-CF-IPC_B 1425,2848 r0 top value=2.2μF
C65 "GRT188R61H225ME13D" FP-C0603C-CF-IPC_B 5575,2848 r0 top value=2.2μF
C66 "CL31B106KAHSFNE" FP-CL31-IPC_B 875,2760 r90 top value=10μF
C67 "CL31B106KAHSFNE" FP-CL31-IPC_B 2135,2765 r180 top value=10μF
C68 "CL31B106KAHSFNE" FP-CL31-IPC_B 4865,2765 r0 top value=10μF
C69 "C0603C472K3RAC7867" FP-C0603C-CF-IPC_B 6290,2773.96 r180 top value=4.7nF
C70 "C0603C472K3RAC7867" FP-C0603C-CF-IPC_B 6290,2703.96 r180 top value=4.7nF
C71 "CL31B106KAHSFNE" FP-CL31-IPC_B 2135,2680 r0 top value=10μF
C72 "CL31B106KAHSFNE" FP-CL31-IPC_B 4865,2680 r180 top value=10μF
C73 "CL31B106KAHSFNE" FP-CL31-IPC_B 1135,2352 r180 top value=10μF
C74 "CL31B106KAHSFNE" FP-CL31-IPC_B 5865,2352 r180 top value=10μF
C75 "GRT188R61H225ME13D" FP-C0603C-CF-IPC_B 1425,2352 r180 top value=2.2μF
C76 "GRT188R61H225ME13D" FP-C0603C-CF-IPC_B 5575,2352 r180 top value=2.2μF
C77 "CL31B106KAHSFNE" FP-CL31-IPC_B 1930,2335 r180 top value=10μF
C78 "CL31B106KAHSFNE" FP-CL31-IPC_B 5070,2335 r180 top value=10μF
C79 "CL10C560JB8NNNC" FP-C0603C-CF-IPC_B 1425,2284 r180 top value=56pF
C80 "CL10C560JB8NNNC" FP-C0603C-CF-IPC_B 5575,2284 r0 top value=56pF
C81 "CL10C560JB8NNNC" FP-C0603C-CF-IPC_B 1425,2216 r180 top value=56pF
C82 "CL10C560JB8NNNC" FP-C0603C-CF-IPC_B 5575,2216 r0 top value=56pF
C83 "CL31B106KAHSFNE" FP-CL31-IPC_B 1930,2145 r0 top value=10μF
C84 "CL31B106KAHSFNE" FP-CL31-IPC_B 5070,2145 r0 top value=10μF
C85 "GRT188R61H225ME13D" FP-C0603C-CF-IPC_B 1425,2148 r0 top value=2.2μF
C86 "GRT188R61H225ME13D" FP-C0603C-CF-IPC_B 5575,2148 r0 top value=2.2μF
C87 "CL31B106KAHSFNE" FP-CL31-IPC_B 2135,2065 r180 top value=10μF
C88 "CL31B106KAHSFNE" FP-CL31-IPC_B 4865,2065 r0 top value=10μF
C89 "CL31B106KAHSFNE" FP-CL31-IPC_B 2135,1980 r0 top value=10μF
C90 "CL31B106KAHSFNE" FP-CL31-IPC_B 4865,1980 r180 top value=10μF
C91 "CL31B106KAHSFNE" FP-CL31-IPC_B 1135,1652 r180 top value=10μF
C92 "CL31B106KAHSFNE" FP-CL31-IPC_B 5865,1652 r180 top value=10μF
C93 "C0603C104K3RACTU" FP-C0603C-CF-IPC_B 7050,1363 r0 top value=0.10μF (schematic designator C94)
C94 "CL10B103KA8WPNC" FP-C0603C-CF-IPC_B 7170,1295 r180 top value=10nF (schematic designator C95)
C95 "C0603C102K5RACAUTO" FP-C0603C-CF-IPC_B 7050,1227 r180 top value=1nF (schematic designator C97)
C96 "C0603C104K3RACTU" FP-C0603C-CF-IPC_B 7560,1160 r90 top value=0.10μF (schematic designator C98)
C97 "06035A180JAT2A" FP-C0603C-CF-IPC_B 7320,1091 r0 top value=18pF (schematic designator C99)
C98 "CL10B103KA8WPNC" FP-C0603C-CF-IPC_B 7170,1022 r0 top value=10nF (schematic designator C101)
C99 "GCM188R72A103KA37D" FP-C0603C-CF-IPC_B 5615,980 r180 top value=10nF (schematic designator C195)
C100 "GCM1885C2A221JA16D" FP-C0603C-CF-IPC_B 6275,981 r180 top value=220pF (schematic designator C218)
C101 "CL10C101JB8NNNC" FP-C0603C-CF-IPC_B 6395,981 r0 top value=100pF (schematic designator C216)
C102 "C0603C102K5RACAUTO" FP-C0603C-CF-IPC_B 5615,910 r180 top value=1nF (schematic designator C96)
C103 "CGA3E2X7R1H683K080AA" FP-C0603C-CF-IPC_B 6155,913 r0 top value=68nF (schematic designator C204)
C104 "C0603C104K3RACTU" FP-C0603C-CF-IPC_B 7320,840 r0 top value=0.10μF (schematic designator C102)
C105 "GCM188R72A103KA37D" FP-C0603C-CF-IPC_B 6650,819 r0 top value=10nF (schematic designator C203)
C106 "C0603C104K3RACTU" FP-C0603C-CF-IPC_B 7320,771 r0 top value=0.10μF (schematic designator C103)
C107 "CGA3E1X7R1V105K080AC" FP-C0603C-CF-IPC_B 6650,750 r0 top value=1μF (schematic designator C201)
C108 "C0603C472K3RAC7867" FP-C0603C-CF-IPC_B 6850,710 r0 top value=4.7nF (schematic designator C107)
C109 "GRM188R6YA106MA73D" FP-C0603C-CF-IPC_B 6120,680 r270 top value=10μF (schematic designator C202)
C110 "GRM188R6YA106MA73D" FP-C0603C-CF-IPC_B 6189,680 r270 top value=10μF (schematic designator C205)
C111 "GRM188R6YA106MA73D" FP-C0603C-CF-IPC_B 6258,680 r270 top value=10μF (schematic designator C186)
C112 "GRM188R6YA106MA73D" FP-C0603C-CF-IPC_B 6327,680 r270 top value=10μF (schematic designator C200)
C113 "CL10C560JB8NNNC" FP-C0603C-CF-IPC_B 6650,478 r180 top value=56pF (schematic designator C108)
C114 "C4AQQEW5650A3BJ" C4AQQEW5650A3BJ 5350,5850 r270 bottom value=65µF (schematic designator C111)
C115 "C4AQQEW5650A3BJ" C4AQQEW5650A3BJ 3500,5850 r90 bottom value=65µF (schematic designator C110)
C116 "C4AQQEW5650A3BJ" C4AQQEW5650A3BJ 1650,5850 r270 bottom value=65µF (schematic designator C112)
C117 "CL10B103KA8WPNC" FP-C0603C-CF-IPC_B 7660,6040 r270 bottom value=10nF (schematic designator C113)
C118 "CL10B103KA8WPNC" FP-C0603C-CF-IPC_B 7300,6040 r270 bottom value=10nF (schematic designator C114)
C119 "CL10B103KA8WPNC" FP-C0603C-CF-IPC_B 6940,6040 r270 bottom value=10nF (schematic designator C115)
C120 "C0603C472K3RAC7867" FP-C0603C-CF-IPC_B 6580,6040 r270 bottom value=4.7nF (schematic designator C116)
C121 "C0603C104K3RACTU" FP-C0603C-CF-IPC_B 7480,5920 r0 bottom value=0.10μF (schematic designator C117)
C122 "C0603C104K3RACTU" FP-C0603C-CF-IPC_B 7480,5710 r0 bottom value=0.10μF (schematic designator C118)
C123 "C0603C104K3RACTU" FP-C0603C-CF-IPC_B 7100,4617 r0 bottom value=0.10μF (schematic designator C119)
C124 "GCM188R71C274KA37D" FP-GCM188-0_1-IPC_A 6790,4564 r180 bottom value=0.27μF (schematic designator C120)
C125 "GCM188R71C274KA37D" FP-GCM188-0_1-IPC_A 6790,4492 r180 bottom value=0.27μF (schematic designator C121)
C126 "CL31B106KAHSFNE" FP-CL31-IPC_B 7850,4395 r90 bottom value=10μF (schematic designator C122)
C127 "GCM188R71C274KA37D" FP-GCM188-0_1-IPC_A 6790,4420 r180 bottom value=0.27μF (schematic designator C123)
C128 "C0603C472K3RAC7867" FP-C0603C-CF-IPC_B 7230,4411 r180 bottom value=4.7nF (schematic designator C124)
C129 "CL10C101JB8NNNC" FP-C0603C-CF-IPC_B 7100,4411 r180 bottom value=100pF (schematic designator C125)
C130 "CL10C101JB8NNNC" FP-C0603C-CF-IPC_B 6970,4411 r0 bottom value=100pF (schematic designator C126)
C131 "C0603C104K3RACTU" FP-C0603C-CF-IPC_B 6475,4355 r270 bottom value=0.10μF (schematic designator C127)
C132 "GCM188R71C274KA37D" FP-GCM188-0_1-IPC_A 6790,4350 r180 bottom value=0.27μF (schematic designator C128)
C133 "C0603C104K3RACTU" FP-C0603C-CF-IPC_B 7100,4343 r0 bottom value=0.10μF (schematic designator C129)
C134 "C0603C472K3RAC7867" FP-C0603C-CF-IPC_B 7230,4139 r180 bottom value=4.7nF (schematic designator C130)
C135 "CL10C101JB8NNNC" FP-C0603C-CF-IPC_B 7100,4139 r180 bottom value=100pF (schematic designator C131)
C136 "CL10C101JB8NNNC" FP-C0603C-CF-IPC_B 6970,4139 r0 bottom value=100pF (schematic designator C132)
C137 "C0603C104K3RACTU" FP-C0603C-CF-IPC_B 7100,4070 r0 bottom value=0.10μF (schematic designator C133)
C138 "C0603C104K3RACTU" FP-C0603C-CF-IPC_B 7885,3868 r0 bottom value=0.10μF (schematic designator C134)
C139 "C0603C104K3RACTU" FP-C0603C-CF-IPC_B 7535,3868 r180 bottom value=0.10μF (schematic designator C135)
C140 "C0603C472K3RAC7867" FP-C0603C-CF-IPC_B 7230,3868 r180 bottom value=4.7nF (schematic designator C136)
C141 "CL10C101JB8NNNC" FP-C0603C-CF-IPC_B 7100,3868 r180 bottom value=100pF (schematic designator C137)
C142 "CL10C101JB8NNNC" FP-C0603C-CF-IPC_B 6970,3868 r0 bottom value=100pF (schematic designator C138)
C143 "CL10C560JB8NNNC" FP-C0603C-CF-IPC_B 6765,3500 r0 bottom value=56pF (schematic designator C139)
C144 "GRT188R61H225ME13D" FP-C0603C-CF-IPC_B 6625,3500 r0 bottom value=2.2μF (schematic designator C140)
C145 "CL10C560JB8NNNC" FP-C0603C-CF-IPC_B 6790,3261 r180 bottom value=56pF (schematic designator C141)
C146 "CL10C560JB8NNNC" FP-C0603C-CF-IPC_B 6790,3192 r180 bottom value=56pF (schematic designator C142)
C147 "C0603C104K3RACTU" FP-C0603C-CF-IPC_B 6650,3192 r0 bottom value=0.10μF (schematic designator C143)
C148 "CL10C560JB8NNNC" FP-C0603C-CF-IPC_B 6790,3123 r180 bottom value=56pF (schematic designator C144)
C149 "CL10C560JB8NNNC" FP-C0603C-CF-IPC_B 6790,3054 r180 bottom value=56pF (schematic designator C145)
C150 "C0603C104K3RACTU" FP-C0603C-CF-IPC_B 6650,3054 r0 bottom value=0.10μF (schematic designator C146)
C151 "C0603C104K3RACTU" FP-C0603C-CF-IPC_B 7065,2986.42 r270 bottom value=0.10μF (schematic designator C147)
C152 "CL10C560JB8NNNC" FP-C0603C-CF-IPC_B 6790,2985 r180 bottom value=56pF (schematic designator C148)
C153 "C0603C104K3RACTU" FP-C0603C-CF-IPC_B 6650,2985 r180 bottom value=0.10μF (schematic designator C149)
C154 "CL10C560JB8NNNC" FP-C0603C-CF-IPC_B 6790,2915 r180 bottom value=56pF (schematic designator C150)
C155 "C0603C104K3RACTU" FP-C0603C-CF-IPC_B 7030,2785 r0 bottom value=0.10μF (schematic designator C151)
C156 "C0603C104K3RACTU" FP-C0603C-CF-IPC_B 7030,2716 r0 bottom value=0.10μF (schematic designator C152)
C157 "GRT188R61H225ME13D" FP-C0603C-CF-IPC_B 7490,2625 r0 bottom value=2.2μF (schematic designator C153)
C158 "CL31B106KAHSFNE" FP-CL31-IPC_B 7140,1840 r270 bottom value=10μF (schematic designator C154)
C159 "CL31B106KAHSFNE" FP-CL31-IPC_B 6765,1840 r270 bottom value=10μF (schematic designator C155)
C160 "CL31B106KAHSFNE" FP-CL31-IPC_B 7140,1640 r90 bottom value=10μF (schematic designator C156)
C161 "CL31B106KAHSFNE" FP-CL31-IPC_B 6765,1640 r90 bottom value=10μF (schematic designator C157)
C162 "CL31B475KBHNFNE" FP-CL31-IPC_C 5380,1360 r0 bottom value=4.7μF (schematic designator C161)
C163 "CL31B475KBHNFNE" FP-CL31-IPC_C 3990,1360 r0 bottom value=4.7μF (schematic designator C162)
C164 "CL31B475KBHNFNE" FP-CL31-IPC_C 2600,1360 r0 bottom value=4.7μF (schematic designator C163)
C165 "C0603C104K3RACTU" FP-C0603C-CF-IPC_B 7800,1285 r180 bottom value=0.10μF (schematic designator C164)
C166 "CL31B475KBHNFNE" FP-CL31-IPC_C 5380,1250 r180 bottom value=4.7μF (schematic designator C165)
C167 "CL31B475KBHNFNE" FP-CL31-IPC_C 3990,1250 r180 bottom value=4.7μF (schematic designator C166)
C168 "CL31B475KBHNFNE" FP-CL31-IPC_C 2600,1250 r180 bottom value=4.7μF (schematic designator C167)
C169 "C0603C331JAGAC7867" FP-C0603C-CF-IPC_B 7800,1215 r180 bottom value=330pF (schematic designator C168)
C170 "C0603C472K3RAC7867" FP-C0603C-CF-IPC_B 6960,1194 r180 bottom value=4.7nF (schematic designator C169)
C171 "06035A180JAT2A" FP-C0603C-CF-IPC_B 7200,1126 r180 bottom value=18pF (schematic designator C170)
C172 "CGA3E2X7R1H473K080AA" FP-C0603C-CF-IPC_B 6155,1038 r180 bottom value=47nF (schematic designator C215)
C173 "C0603C104K3RACTU" FP-C0603C-CF-IPC_B 7200,990 r0 bottom value=0.10μF (schematic designator C171)
C174 "C0603C104K3RACTU" FP-C0603C-CF-IPC_B 6960,990 r0 bottom value=0.10μF (schematic designator C172)
C175 "GCM188R71E224KA55D" FP-C0603C-CF-IPC_B 6155,900 r180 bottom value=220nF (schematic designator C217)
C176 "CGA3E2X7R1H104K080AA" FP-C0603C-CF-IPC_B 5755,900 r180 bottom value=100nF (schematic designator C196)
C177 "C0603C470J1GACTU" FP-C0603C-CF-IPC_B 7620,865 r90 bottom value=47pF (schematic designator C173)
C178 "C0603C331JAGAC7867" FP-C0603C-CF-IPC_B 7290,865 r90 bottom value=330pF (schematic designator C174)
C179 "GRM188R6YA106MA73D" FP-C0603C-CF-IPC_B 5755,830 r180 bottom value=10μF (schematic designator C197)
C180 "C0603C470J1GACTU" FP-C0603C-CF-IPC_B 7620,745 r90 bottom value=47pF (schematic designator C175)
C181 "C0603C331JAGAC7867" FP-C0603C-CF-IPC_B 7290,745 r90 bottom value=330pF (schematic designator C176)
C182 "GRM188R6YA106MA73D" FP-C0603C-CF-IPC_B 5755,760 r180 bottom value=10μF (schematic designator C198)
C183 "GRM188R6YA106MA73D" FP-C0603C-CF-IPC_B 5755,690 r180 bottom value=10μF (schematic designator C199)
C184 "C0603C104K3RACTU" FP-C0603C-CF-IPC_B 7680,652 r0 bottom value=0.10μF (schematic designator C177)
C185 "C0603C331JAGAC7867" FP-C0603C-CF-IPC_B 7800,583 r0 bottom value=330pF (schematic designator C178)
C186 "C0603C104K3RACTU" FP-C0603C-CF-IPC_B 7680,583 r0 bottom value=0.10μF (schematic designator C179)
C187 "C0603C104K3RACTU" FP-C0603C-CF-IPC_B 7800,513 r0 bottom value=0.10μF (schematic designator C180)
C188 "C0603C104K3RACTU" FP-C0603C-CF-IPC_B 7680,513 r0 bottom value=0.10μF (schematic designator C181)
C189 "C0603C681J5GACTU" FP-C0603C-CF-IPC_B 6405,300 r90 bottom value=680pF (schematic designator C187)
C190 "GRM188R6YA106MA73D" FP-C0603C-CF-IPC_B 6335,300 r270 bottom value=10μF (schematic designator C193)
C191 "GRM188R6YA106MA73D" FP-C0603C-CF-IPC_B 6265,300 r270 bottom value=10μF (schematic designator C194)
C192 "CGA3E1X7R1V105K080AC" FP-C0603C-CF-IPC_B 6195,300 r270 bottom value=1μF (schematic designator C93)
C193 "CGA3E2X7R1H104K080AA" FP-C0603C-CF-IPC_B 6125,300 r270 bottom value=100nF (schematic designator C188)
C194 "CGA3E2X7R1H104K080AA" FP-C0603C-CF-IPC_B 6055,300 r90 bottom value=100nF (schematic designator C206)
C195 "CGA3E1X7R1V105K080AC" FP-C0603C-CF-IPC_B 5985,300 r90 bottom value=1μF (schematic designator C207)
C196 "GRM188R6YA106MA73D" FP-C0603C-CF-IPC_B 5915,300 r90 bottom value=10μF (schematic designator C208)
C197 "GRM188R6YA106MA73D" FP-C0603C-CF-IPC_B 5845,300 r90 bottom value=10μF (schematic designator C209)
C198 "C0603C681J5GACTU" FP-C0603C-CF-IPC_B 5775,300 r90 bottom value=680pF (schematic designator C214)
C199 "GRM188R6YA106MA73D" FP-C0603C-CF-IPC_B 6335,130 r90 bottom value=10μF (schematic designator C192)
C200 "GRM188R6YA106MA73D" FP-C0603C-CF-IPC_B 6265,130 r90 bottom value=10μF (schematic designator C191)
C201 "GRM188R6YA106MA73D" FP-C0603C-CF-IPC_B 6195,130 r90 bottom value=10μF (schematic designator C190)
C202 "GRM188R6YA106MA73D" FP-C0603C-CF-IPC_B 6125,130 r90 bottom value=10μF (schematic designator C189)
C203 "GRM188R6YA106MA73D" FP-C0603C-CF-IPC_B 6055,130 r270 bottom value=10μF (schematic designator C212)
C204 "GRM188R6YA106MA73D" FP-C0603C-CF-IPC_B 5985,130 r270 bottom value=10μF (schematic designator C213)
C205 "GRM188R6YA106MA73D" FP-C0603C-CF-IPC_B 5915,130 r270 bottom value=10μF (schematic designator C211)
C206 "GRM188R6YA106MA73D" FP-C0603C-CF-IPC_B 5845,130 r270 bottom value=10μF (schematic designator C210)
C207 "CL31B106KAHSFNE" FP-CL31-IPC_B 6850,105 r0 bottom value=10μF (schematic designator C185)
D1 "CMD17-21VRD/TR8" FP-LTST-C171GKT-MFG-RED 7420,3012 r0 top value=RED
D2 "LTST-C171KSKT" FP-LTST-C171GKT-MFG-YELLOW 7420,2930 r0 top value=YELLOW
D3 "LTST-C171GKT" FP-LTST-C171GKT-MFG 7420,2848 r0 top value=GREEN
D4 "LTST-C171GKT" FP-LTST-C171GKT-MFG 6645,1420 r0 top value=GREEN (schematic designator D6)
D5 "LTST-C171GKT" FP-LTST-C171GKT-MFG 6645,1335 r0 top value=GREEN (schematic designator D7)
D6 "LTST-C171GKT" FP-LTST-C171GKT-MFG 6645,1250 r0 top value=GREEN (schematic designator D8)
D7 "LTST-C171GKT" FP-LTST-C171GKT-MFG 6645,1170 r0 top value=GREEN (schematic designator D9)
D8 "BAS40DW-04-TP" SOT65P222X120-6N 7550,1020 r90 top value=N/A (schematic designator D10)
D9 "BAS40DW-04-TP" SOT65P222X120-6N 7550,840 r90 top value=N/A (schematic designator D11)
D10 "BAS40DW-04-TP" SOT65P222X120-6N 7550,660 r90 top value=N/A (schematic designator D12)
D11 "APTR3216-VFX" FP-APTR3216SECK-MFG 6216.53,3700 r180 bottom value=PURPLE (schematic designator D13)
D12 "APTR3216-VFX" FP-APTR3216SECK-MFG 783.47,3700 r180 bottom value=PURPLE (schematic designator D14)
D13 "APTR3216-VFX" FP-APTR3216SECK-MFG 6216.53,2300 r180 bottom value=PURPLE (schematic designator D15)
D14 "APTR3216-VFX" FP-APTR3216SECK-MFG 783.47,2300 r180 bottom value=PURPLE (schematic designator D16)
D15 "SMD26PL-TP" ONSC-SOD-123FL-2-498-01_V 7865,2000 r0 bottom value=N/A (schematic designator D17)
D16 "SMD26PL-TP" ONSC-SOD-123FL-2-498-01_V 7865,1385 r0 bottom value=N/A (schematic designator D18)
D17 "PMEG060V100EPE-QZ" FP-PSMC_TO-277A-MFG 6215,505 r0 bottom value=N/A (schematic designator D20)
D18 "PMEG060V100EPE-QZ" FP-PSMC_TO-277A-MFG 5965,505 r0 bottom value=N/A (schematic designator D21)
HS1 "LA6/150 12V" "LA 6 150 12" 3500,3000 r180 bottom locked value=N/A
J1 "1755778" 1755778 6750,7835 r180 top value=N/A
J2 "7460307" 7460307 2110,7400 r0 top value=N/A
J3 "7460307" 7460307 4890,7400 r0 top value=N/A
J4 "L717SDE09PA4CH4RC309" L717SDE09PA4CH4RC309 7630,5020 r90 top value=N/A
J5 "0734151471" FP-73415-1471-MFG 2900,3800 r0 top value=N/A
J6 "0734151471" FP-73415-1471-MFG 3500,3800 r0 top value=N/A
J7 "0734151471" FP-73415-1471-MFG 4100,3800 r0 top value=N/A
J8 "61301221121" FP-61301221121-MFG 7887,3400 r270 top value=N/A
J9 "640456-2" TECO-640456-2_V 7887,2930 r90 top value=N/A
J10 "640456-2" TECO-640456-2_V 7887,2625 r90 top value=N/A
J11 "1755736" 1755736 7837,2200 r90 top value=N/A
J12 "0734151471" FP-73415-1471-MFG 2900,2200 r0 top value=N/A
J13 "0734151471" FP-73415-1471-MFG 3500,2200 r0 top value=N/A
J14 "0734151471" FP-73415-1471-MFG 4100,2200 r0 top value=N/A
J15 "1755736" 1755736 7837,1585 r90 top value=N/A
J16 "61200621621" 61200621621 7810,890 r270 top value=N/A
J17 "7460307" 7460307 2110,600 r0 top value=N/A
J18 "7460307" 7460307 3500,600 r0 top value=N/A
J19 "7460307" 7460307 4890,600 r0 top value=N/A
J20 "PJ-102AH" CUI-PJ-102B_V 7170,428.11 r270 top value=N/A
L1 "744226S" WE-SL2 1135,3300 r270 top value=10μH
L2 "744226S" WE-SL2 5865,3300 r270 top value=10μH
L3 "744226S" WE-SL2 1135,2600 r270 top value=10μH
L4 "744226S" WE-SL2 5865,2600 r270 top value=10μH
L5 "744226S" WE-SL2 1135,1900 r270 top value=10μH
L6 "744226S" WE-SL2 5865,1900 r270 top value=10μH
L7 "74439358100" WE-XHMI_8080_L8.8W8.3H7.8 5880,830 r90 top value=10μH (schematic designator L9)
L8 "74437368220" 74437368220 5795,320 r270 top value=22µH (schematic designator L7)
L9 "74437368220" 74437368220 6230,320 r90 top value=22µH (schematic designator L10)
MH1 "MH_M4_P" MH_M4_P 250,7750 r0 top locked value=N/A
MH2 "MH_M4_P" MH_M4_P 7750,7750 r0 top locked value=N/A
MH3 "MH_M4_P" MH_M4_P 250,250 r0 top locked value=N/A
MH4 "MH_M4_P" MH_M4_P 7750,250 r0 top locked value=N/A
Q1 "BC817-16LT3G" ONSC-SOT-23-3-318-08_V 7050,1120 r0 top value=N/A (schematic designator Q2)
Q2 "CCB021M12FM3T" FM3_SIX-PACK_3PHASE_CRW 3500,3000 r0 bottom locked value=N/A (schematic designator Q3)
Q3 "MJD44H11T4G" ONSC-DPAK-3-369C-01_V 7615,2205 r90 bottom value=N/A (schematic designator Q4)
Q4 "MJD44H11T4G" ONSC-DPAK-3-369C-01_V 7615,1590 r90 bottom value=N/A (schematic designator Q5)
Q5 "DMT12H007LPS-13" FP-PowerDI5060-8-MFG 6910,710 r90 bottom value=N/A (schematic designator Q6)
Q6 "DMT12H007LPS-13" FP-PowerDI5060-8-MFG 6910,460 r90 bottom value=N/A (schematic designator Q7)
R1 "CRGP2512F220K" FP-CRGP2512-IPC_C 2900,7650 r180 top value=220kΩ
R2 "CRGP2512F220K" FP-CRGP2512-IPC_C 3300,7650 r180 top value=220kΩ
R3 "CRGP2512F220K" FP-CRGP2512-IPC_C 3700,7650 r180 top value=220kΩ
R4 "CRGP2512F220K" FP-CRGP2512-IPC_C 4100,7650 r180 top value=220kΩ
R5 "CRGP2512F220K" FP-CRGP2512-IPC_C 2900,7450 r180 top value=220kΩ
R6 "CRGP2512F220K" FP-CRGP2512-IPC_C 3300,7450 r180 top value=220kΩ
R7 "CRGP2512F220K" FP-CRGP2512-IPC_C 3700,7450 r180 top value=220kΩ
R8 "CRGP2512F220K" FP-CRGP2512-IPC_C 4100,7450 r180 top value=220kΩ
R9 "CRGP2512F220K" FP-CRGP2512-IPC_C 2900,7250 r180 top value=220kΩ
R10 "CRGP2512F220K" FP-CRGP2512-IPC_C 3300,7250 r180 top value=220kΩ
R11 "CRGP2512F220K" FP-CRGP2512-IPC_C 3700,7250 r180 top value=220kΩ
R12 "CRGP2512F220K" FP-CRGP2512-IPC_C 4100,7250 r180 top value=220kΩ
R13 "TNPW1206249KBEEA" RESC3216X65X50NL15T25 6580,7150 r270 top value=249kΩ
R14 "TNPW1206249KBEEA" RESC3216X65X50NL15T25 6940,7150 r270 top value=249kΩ
R15 "TNPW1206249KBEEA" RESC3216X65X50NL15T25 7300,7150 r270 top value=249kΩ
R16 "TNPW1206249KBEEA" RESC3216X65X50NL15T25 7660,7150 r270 top value=249kΩ
R17 "TNPW1206249KBEEA" RESC3216X65X50NL15T25 6580,6960 r270 top value=249kΩ
R18 "TNPW1206249KBEEA" RESC3216X65X50NL15T25 6940,6960 r270 top value=249kΩ
R19 "TNPW1206249KBEEA" RESC3216X65X50NL15T25 7300,6960 r270 top value=249kΩ
R20 "TNPW1206249KBEEA" RESC3216X65X50NL15T25 7660,6960 r270 top value=249kΩ
R21 "TNPW1206249KBEEA" RESC3216X65X50NL15T25 6580,6770 r270 top value=249kΩ
R22 "TNPW1206249KBEEA" RESC3216X65X50NL15T25 6940,6770 r270 top value=249kΩ
R23 "TNPW1206249KBEEA" RESC3216X65X50NL15T25 7300,6770 r270 top value=249kΩ
R24 "TNPW1206249KBEEA" RESC3216X65X50NL15T25 7660,6770 r270 top value=249kΩ
R25 "TNPW1206249KBEEA" RESC3216X65X50NL15T25 6580,6580 r270 top value=249kΩ
R26 "TNPW1206249KBEEA" RESC3216X65X50NL15T25 6940,6580 r270 top value=249kΩ
R27 "TNPW1206249KBEEA" RESC3216X65X50NL15T25 7300,6580 r270 top value=249kΩ
R28 "TNPW1206249KBEEA" RESC3216X65X50NL15T25 7660,6580 r270 top value=249kΩ
R29 "TNPW1206249KBEEA" RESC3216X65X50NL15T25 6580,6390 r270 top value=249kΩ
R30 "TNPW1206249KBEEA" RESC3216X65X50NL15T25 6940,6390 r270 top value=249kΩ
R31 "TNPW1206249KBEEA" RESC3216X65X50NL15T25 7300,6390 r270 top value=249kΩ
R32 "TNPW1206249KBEEA" RESC3216X65X50NL15T25 7660,6390 r270 top value=249kΩ
R33 "TNPW1206249KBEEA" RESC3216X65X50NL15T25 6580,6200 r270 top value=249kΩ
R34 "TNPW1206249KBEEA" RESC3216X65X50NL15T25 6940,6200 r270 top value=249kΩ
R35 "TNPW1206249KBEEA" RESC3216X65X50NL15T25 7300,6200 r270 top value=249kΩ
R36 "TNPW1206249KBEEA" RESC3216X65X50NL15T25 7660,6200 r270 top value=249kΩ
R37 "RC0603FR-074K99L" FP-MCR03-IPC_B 6580,6040 r270 top value=4.99kΩ
R38 "ERJ-PB3B3741V" FP-MCR03-IPC_B 6700,6040 r90 top value=3.74kΩ
R39 "RC0603FR-074K99L" FP-MCR03-IPC_B 6940,6040 r270 top value=4.99kΩ
R40 "ERJ-PB3B1801V" FP-MCR03-IPC_B 7060,6040 r270 top value=1.8kΩ
R41 "RC0603FR-074K99L" FP-MCR03-IPC_B 7300,6040 r270 top value=4.99kΩ
R42 "ERJ-PB3B1801V" FP-MCR03-IPC_B 7420,6040 r270 top value=1.8kΩ
R43 "RC0603FR-074K99L" FP-MCR03-IPC_B 7660,6040 r270 top value=4.99kΩ
R44 "ERJ-PB3B1801V" FP-MCR03-IPC_B 7780,6040 r270 top value=1.8kΩ
R45 "ERJ-3EKF49R9V" FP-MCR03-IPC_B 6790,4566 r0 top value=49.9Ω
R46 "ERJ3EKF1002V" FP-MCR03-IPC_B 5450,4470 r90 top value=10kΩ (schematic designator R47)
R47 "CRCW060320K0FKTA" FP-MCR03-IPC_B 5518,4470 r90 top value=20kΩ (schematic designator R48)
R48 "ERA3AEB132V" FP-MCR03-IPC_B 5586,4470 r270 top value=1.3kΩ (schematic designator R49)
R49 "RC1608F1542CS" FP-MCR03-IPC_B 5654,4470 r90 top value=15.4kΩ (schematic designator R50)
R50 "ERJ-3EKF49R9V" FP-MCR03-IPC_B 6790,4499 r0 top value=49.9Ω (schematic designator R46)
R51 "CRCW06034K70FKTA" FP-MCR03-IPC_B 5790,4470 r270 top value=4.7kΩ
R52 "ERJ3EKF1002V" FP-MCR03-IPC_B 5858,4470 r270 top value=10kΩ
R53 "CRCW06030000Z0EB" FP-MCR03-IPC_B 5925,4470 r90 top value=0Ω
R54 "ERJ3EKF1002V" FP-MCR03-IPC_B 5992,4470 r90 top value=10kΩ
R55 "ERJ-3EKF49R9V" FP-MCR03-IPC_B 6790,4432 r0 top value=49.9Ω
R56 "RC0603FR-13330RL" FP-MCR03-IPC_B 5710,4340 r90 top value=330Ω (schematic designator R57)
R57 "ERJ-3EKF49R9V" FP-MCR03-IPC_B 6790,4365 r0 top value=49.9Ω (schematic designator R56)
R58 "RT0603DRE072KL" FP-MCR03-IPC_B 7210,4236 r180 top value=2kΩ
R59 "ERJ3EKF1002V" FP-MCR03-IPC_B 5654,4200 r270 top value=10kΩ
R60 "RMCF0603FT249K" FP-MCR03-IPC_B 5722,4200 r90 top value=249kΩ
R61 "ERJ3EKF1002V" FP-MCR03-IPC_B 5790,4200 r90 top value=10kΩ
R62 "ERJ-3EKF9762V" FP-MCR03-IPC_B 5925,4200 r270 top value=97.6kΩ
R63 "RT0603DRE072KL" FP-MCR03-IPC_B 7210,4100 r180 top value=2kΩ
R64 "ERJ-3EKF49R9V" FP-MCR03-IPC_B 6790,4042 r0 top value=49.9Ω
R65 "CRCW06030000Z0EB" FP-MCR03-IPC_B 7210,3964 r180 top value=0Ω
R66 "CRCW06030000Z0EB" FP-MCR03-IPC_B 7210,3896 r180 top value=0Ω
R67 "ERJ3EKF1002V" FP-MCR03-IPC_B 2135,3788 r0 top value=10kΩ
R68 "ERJ3EKF1002V" FP-MCR03-IPC_B 4865,3788 r180 top value=10kΩ
R69 "CRCW12100000Z0EAHP" RESC3125X70X40NL20T20 2135,3688 r0 top value=0Ω
R70 "RCWE1210R910FKEA" RESC3125X70X40NL20T20 4865,3688 r180 top value=0.91Ω
R71 "ERJ-3EKF49R9V" FP-MCR03-IPC_B 1300,3684 r0 top value=49.9Ω
R72 "ERJ-3EKF49R9V" FP-MCR03-IPC_B 5700,3684 r180 top value=49.9Ω
R73 "RC1206FR-07249RL" FP-MCR18-IPC_A 830,3610 r0 top value=249Ω
R74 "RC1206FR-07249RL" FP-MCR18-IPC_A 6170,3610 r0 top value=249Ω
R75 "ERJ-3EKF49R9V" FP-MCR03-IPC_B 1300,3616 r0 top value=49.9Ω
R76 "ERJ-3EKF49R9V" FP-MCR03-IPC_B 5700,3616 r180 top value=49.9Ω
R77 "RCWE1210R910FKEA" RESC3125X70X40NL20T20 2135,3572 r0 top value=0.91Ω
R78 "CRCW12100000Z0EAHP" RESC3125X70X40NL20T20 4865,3572 r180 top value=0Ω
R79 "RC1206FR-07249RL" FP-MCR18-IPC_A 830,3530 r180 top value=249Ω
R80 "RC1206FR-07249RL" FP-MCR18-IPC_A 6170,3530 r0 top value=249Ω
R81 "ERJ-3EKF49R9V" FP-MCR03-IPC_B 6790,3480 r180 top value=49.9Ω
R82 "ERA3AEB132V" FP-MCR03-IPC_B 6290,3386 r180 top value=1.3kΩ
R83 "ERJ3EKF1002V" FP-MCR03-IPC_B 6290,3319 r0 top value=10kΩ
R84 "ERJ-3EKF49R9V" FP-MCR03-IPC_B 6790,3256 r0 top value=49.9Ω
R85 "ERJ-3EKF49R9V" FP-MCR03-IPC_B 6790,3189 r0 top value=49.9Ω
R86 "ERJ-3EKF49R9V" FP-MCR03-IPC_B 6790,3122 r0 top value=49.9Ω
R87 "ERJ-3EKF49R9V" FP-MCR03-IPC_B 6290,3114 r0 top value=49.9Ω
R88 "ERJ3EKF1002V" FP-MCR03-IPC_B 2135,3088 r0 top value=10kΩ
R89 "ERJ3EKF1002V" FP-MCR03-IPC_B 4865,3088 r180 top value=10kΩ
R90 "ERJ-3EKF49R9V" FP-MCR03-IPC_B 6790,3055 r0 top value=49.9Ω
R91 "ERJ3EKF1002V" FP-MCR03-IPC_B 6290,3045.96 r180 top value=10kΩ
R92 "CRCW12100000Z0EAHP" RESC3125X70X40NL20T20 2135,2988 r0 top value=0Ω
R93 "RCWE1210R910FKEA" RESC3125X70X40NL20T20 4865,2988 r180 top value=0.91Ω
R94 "ERJ-3EKF49R9V" FP-MCR03-IPC_B 1300,2984 r0 top value=49.9Ω (schematic designator R95)
R95 "ERJ-3EKF49R9V" FP-MCR03-IPC_B 5700,2984 r180 top value=49.9Ω (schematic designator R96)
R96 "ERJ-3EKF49R9V" FP-MCR03-IPC_B 6790,2988 r0 top value=49.9Ω (schematic designator R94)
R97 "ERA3AEB132V" FP-MCR03-IPC_B 6290,2977.96 r0 top value=1.3kΩ
R98 "ERJ-3EKF49R9V" FP-MCR03-IPC_B 1300,2916 r0 top value=49.9Ω (schematic designator R99)
R99 "ERJ-3EKF49R9V" FP-MCR03-IPC_B 5700,2916 r180 top value=49.9Ω (schematic designator R100)
R100 "ERJ-3EKF49R9V" FP-MCR03-IPC_B 6790,2921 r0 top value=49.9Ω (schematic designator R98)
R101 "RCWE1210R910FKEA" RESC3125X70X40NL20T20 2135,2872 r0 top value=0.91Ω
R102 "CRCW12100000Z0EAHP" RESC3125X70X40NL20T20 4865,2872 r180 top value=0Ω
R103 "ERJ-3EKF49R9V" FP-MCR03-IPC_B 6290,2841.96 r0 top value=49.9Ω
R104 "ERJ-3EKF49R9V" FP-MCR03-IPC_B 6290,2634.96 r0 top value=49.9Ω
R105 "RC2010FK-07100RL" RESC2010(5025)_N 6510,2530 r0 top value=100Ω
R106 "RT0603DRE072KL" FP-MCR03-IPC_B 6685,2535 r0 top value=2kΩ
R107 "RC1206FR-07249RL" FP-MCR18-IPC_A 830,2470 r180 top value=249Ω
R108 "RC1206FR-07249RL" FP-MCR18-IPC_A 6170,2470 r0 top value=249Ω
R109 "RC2010FK-07100RL" RESC2010(5025)_N 6510,2400 r0 top value=100Ω
R110 "RC1206FR-07249RL" FP-MCR18-IPC_A 830,2390 r180 top value=249Ω
R111 "RC1206FR-07249RL" FP-MCR18-IPC_A 6170,2390 r0 top value=249Ω
R112 "ERJ3EKF1002V" FP-MCR03-IPC_B 2135,2388 r0 top value=10kΩ
R113 "ERJ3EKF1002V" FP-MCR03-IPC_B 4865,2388 r180 top value=10kΩ
R114 "RT0603DRE072KL" FP-MCR03-IPC_B 6685,2385 r0 top value=2kΩ
R115 "CRCW12100000Z0EAHP" RESC3125X70X40NL20T20 2135,2288 r0 top value=0Ω
R116 "RCWE1210R910FKEA" RESC3125X70X40NL20T20 4865,2288 r180 top value=0.91Ω
R117 "RC2010FK-07100RL" RESC2010(5025)_N 6510,2270 r0 top value=100Ω
R118 "ERJ-3EKF49R9V" FP-MCR03-IPC_B 1300,2284 r0 top value=49.9Ω
R119 "ERJ-3EKF49R9V" FP-MCR03-IPC_B 5700,2284 r180 top value=49.9Ω
R120 "RT0603DRE072KL" FP-MCR03-IPC_B 6685,2235 r0 top value=2kΩ
R121 "ERJ-3EKF49R9V" FP-MCR03-IPC_B 1300,2216 r0 top value=49.9Ω
R122 "ERJ-3EKF49R9V" FP-MCR03-IPC_B 5700,2216 r180 top value=49.9Ω
R123 "RCWE1210R910FKEA" RESC3125X70X40NL20T20 2135,2172 r0 top value=0.91Ω
R124 "CRCW12100000Z0EAHP" RESC3125X70X40NL20T20 4865,2172 r180 top value=0Ω
R125 "CRCW12100000Z0EAHP" RESC3125X70X40NL20T20 6180,1710 r90 top value=0Ω
R126 "CRCW12100000Z0EAHP" RESC3125X70X40NL20T20 6310,1710 r90 top value=0Ω
R127 "ERJ3EKF1002V" FP-MCR03-IPC_B 7050,1432 r0 top value=10kΩ
R128 "CRCW060320K0FKTA" FP-MCR03-IPC_B 7170,1432 r180 top value=20kΩ
R129 "RC0603FR-07100KL" FP-MCR03-IPC_B 7170,1363 r0 top value=100kΩ (schematic designator R132)
R130 "ERJ3EKF1002V" FP-MCR03-IPC_B 7050,1295 r180 top value=10kΩ (schematic designator R133)
R131 "ERJ3EKF1002V" FP-MCR03-IPC_B 7170,1227 r180 top value=10kΩ (schematic designator R134)
R132 "RC0603JR-0720RL" FP-MCR03-IPC_B 7170,1159 r0 top value=20Ω (schematic designator R135)
R133 "ERJ3EKF1002V" FP-MCR03-IPC_B 7170,1091 r180 top value=10kΩ (schematic designator R136)
R134 "RC0603FR-075K49L" FP-MCR03-IPC_B 6155,1045 r0 top value=5.49kΩ (schematic designator R256)
R135 "RC0603FR-07470KL" FP-MCR03-IPC_B 7320,1022 r0 top value=470kΩ (schematic designator R138)
R136 "RT0603DRE0771K5L" FP-MCR03-IPC_B 6155,980 r180 top value=71.5kΩ (schematic designator R254)
R137 "RT0603FRE0749K9L" FP-MCR03-IPC_B 6650,956 r180 top value=49.9kΩ (schematic designator R259)
R138 "RC0603FR-07100KL" FP-MCR03-IPC_B 7170,954 r180 top value=100kΩ (schematic designator R141)
R139 "RC0603FR-0724K9L" FP-MCR03-IPC_B 6650,888 r0 top value=24.9kΩ (schematic designator R255)
R140 "CRCW060320K0FKTA" FP-MCR03-IPC_B 7170,886 r0 top value=20kΩ (schematic designator R142)
R141 "RC0603FR-0761K9L" FP-MCR03-IPC_B 6155,844 r0 top value=61.9kΩ (schematic designator R260)
R142 "RC0603FR-07100KL" FP-MCR03-IPC_B 6650,682 r0 top value=100kΩ (schematic designator R143)
R143 "RT0603DRE072KL" FP-MCR03-IPC_B 6850,640 r0 top value=2kΩ (schematic designator R150)
R144 "RC0603FR-07100KL" FP-MCR03-IPC_B 6650,614 r180 top value=100kΩ
R145 "CRCW060320K0FKTA" FP-MCR03-IPC_B 6850,570 r180 top value=20kΩ (schematic designator R148)
R146 "RC0603FR-07100KL" FP-MCR03-IPC_B 6650,546 r180 top value=100kΩ (schematic designator R147)
R147 "RC0603JR-072M7L" FP-MCR03-IPC_B 6650,410 r0 top value=2.7MΩ (schematic designator R149)
R148 "RC0603JR-072M7L" FP-MCR03-IPC_B 6650,342 r180 top value=2.7MΩ (schematic designator R151)
R149 "TNPW1206249KBEEA" RESC3216X65X50NL15T25 7660,7150 r270 bottom value=249kΩ (schematic designator R156)
R150 "TNPW1206249KBEEA" RESC3216X65X50NL15T25 7300,7150 r270 bottom value=249kΩ (schematic designator R157)
R151 "TNPW1206249KBEEA" RESC3216X65X50NL15T25 6940,7150 r270 bottom value=249kΩ (schematic designator R158)
R152 "TNPW1206249KBEEA" RESC3216X65X50NL15T25 6580,7150 r270 bottom value=249kΩ (schematic designator R159)
R153 "TNPW1206249KBEEA" RESC3216X65X50NL15T25 7660,6960 r270 bottom value=249kΩ (schematic designator R160)
R154 "TNPW1206249KBEEA" RESC3216X65X50NL15T25 7300,6960 r270 bottom value=249kΩ (schematic designator R161)
R155 "TNPW1206249KBEEA" RESC3216X65X50NL15T25 6940,6960 r270 bottom value=249kΩ (schematic designator R162)
R156 "TNPW1206249KBEEA" RESC3216X65X50NL15T25 6580,6960 r270 bottom value=249kΩ (schematic designator R163)
R157 "TNPW1206249KBEEA" RESC3216X65X50NL15T25 7660,6770 r270 bottom value=249kΩ (schematic designator R164)
R158 "TNPW1206249KBEEA" RESC3216X65X50NL15T25 7300,6770 r270 bottom value=249kΩ (schematic designator R165)
R159 "TNPW1206249KBEEA" RESC3216X65X50NL15T25 6940,6770 r270 bottom value=249kΩ (schematic designator R166)
R160 "TNPW1206249KBEEA" RESC3216X65X50NL15T25 6580,6770 r270 bottom value=249kΩ (schematic designator R167)
R161 "TNPW1206249KBEEA" RESC3216X65X50NL15T25 7660,6580 r270 bottom value=249kΩ (schematic designator R168)
R162 "TNPW1206249KBEEA" RESC3216X65X50NL15T25 7300,6580 r270 bottom value=249kΩ (schematic designator R169)
R163 "TNPW1206249KBEEA" RESC3216X65X50NL15T25 6940,6580 r270 bottom value=249kΩ (schematic designator R170)
R164 "TNPW1206249KBEEA" RESC3216X65X50NL15T25 6580,6580 r270 bottom value=249kΩ (schematic designator R171)
R165 "TNPW1206249KBEEA" RESC3216X65X50NL15T25 7660,6390 r270 bottom value=249kΩ (schematic designator R172)
R166 "TNPW1206249KBEEA" RESC3216X65X50NL15T25 7300,6390 r270 bottom value=249kΩ (schematic designator R173)
R167 "TNPW1206249KBEEA" RESC3216X65X50NL15T25 6940,6390 r270 bottom value=249kΩ (schematic designator R174)
R168 "TNPW1206249KBEEA" RESC3216X65X50NL15T25 6580,6390 r270 bottom value=249kΩ (schematic designator R175)
R169 "TNPW1206249KBEEA" RESC3216X65X50NL15T25 7660,6200 r270 bottom value=249kΩ (schematic designator R176)
R170 "TNPW1206249KBEEA" RESC3216X65X50NL15T25 7300,6200 r270 bottom value=249kΩ (schematic designator R177)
